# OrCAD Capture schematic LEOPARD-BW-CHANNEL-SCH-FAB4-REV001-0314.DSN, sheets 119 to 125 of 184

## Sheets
119 052_DDR4 DIMM CPU0 CHA-1: size A3; title: DDR4 DIMM CPU0 CHA-1
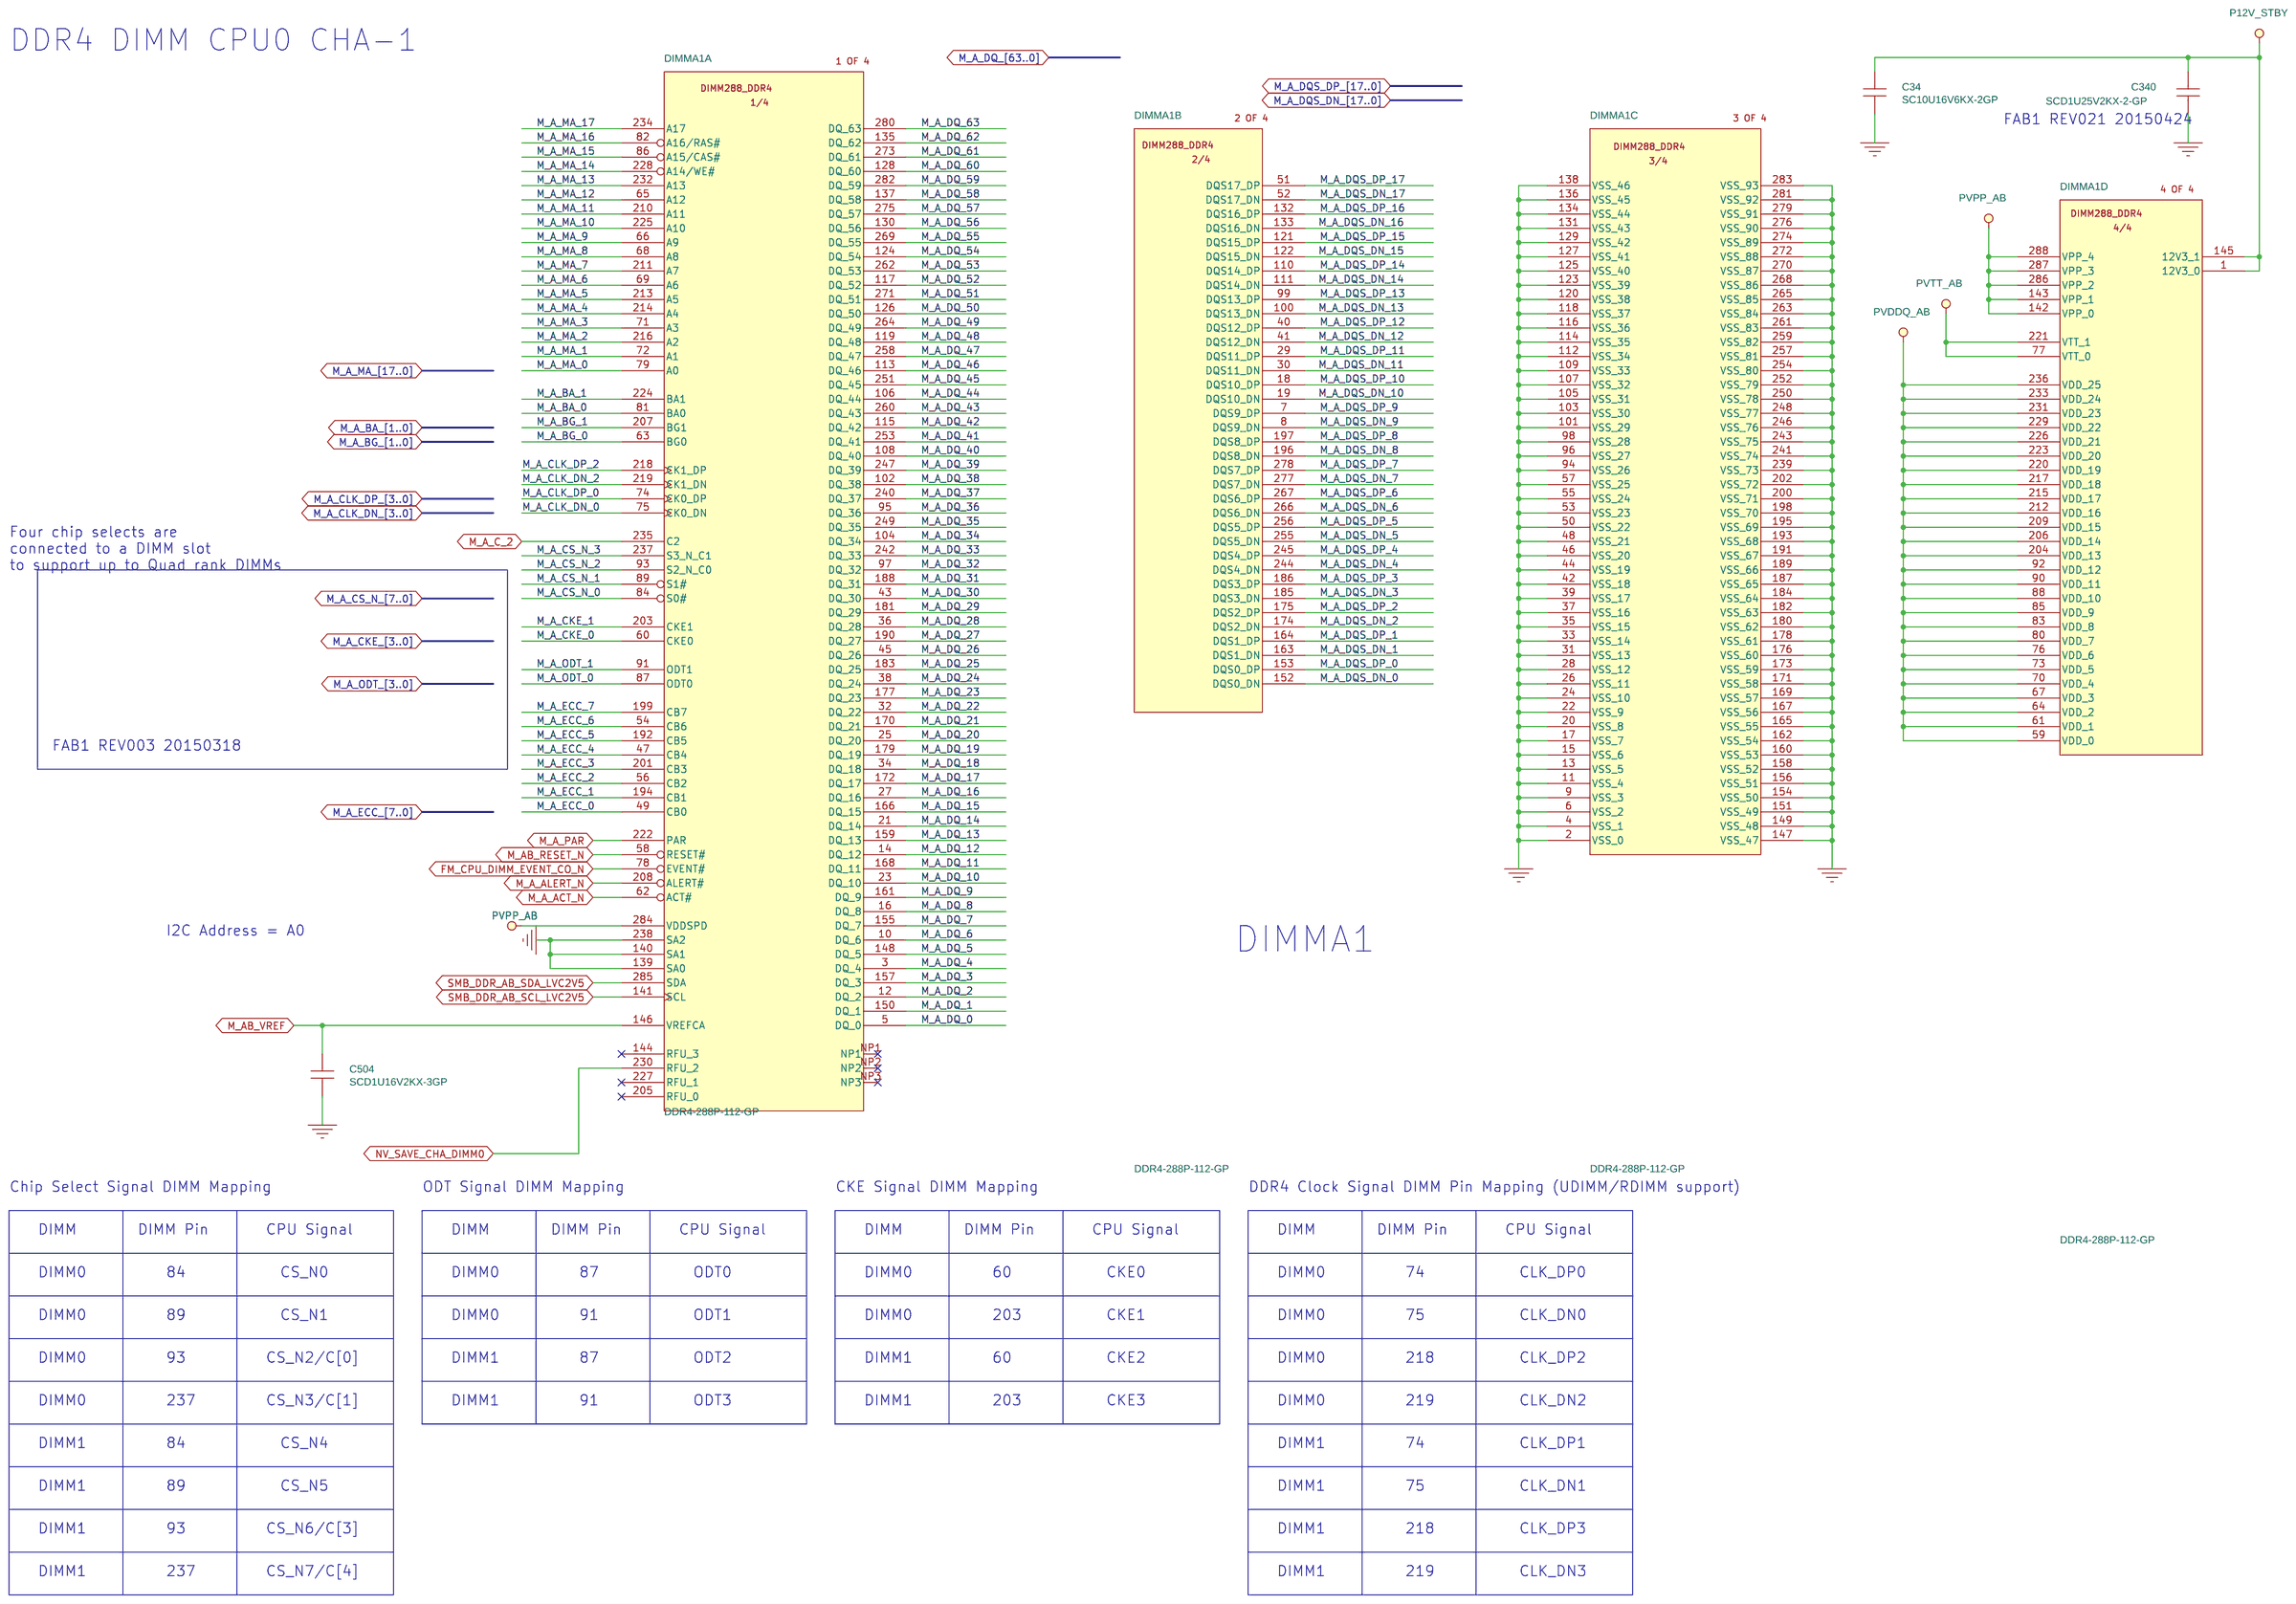
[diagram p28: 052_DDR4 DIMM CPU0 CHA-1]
120 049_CPU2 - VCCIN & VDDQ: size A3; title: CPU2 - VCCIN & VDDQ
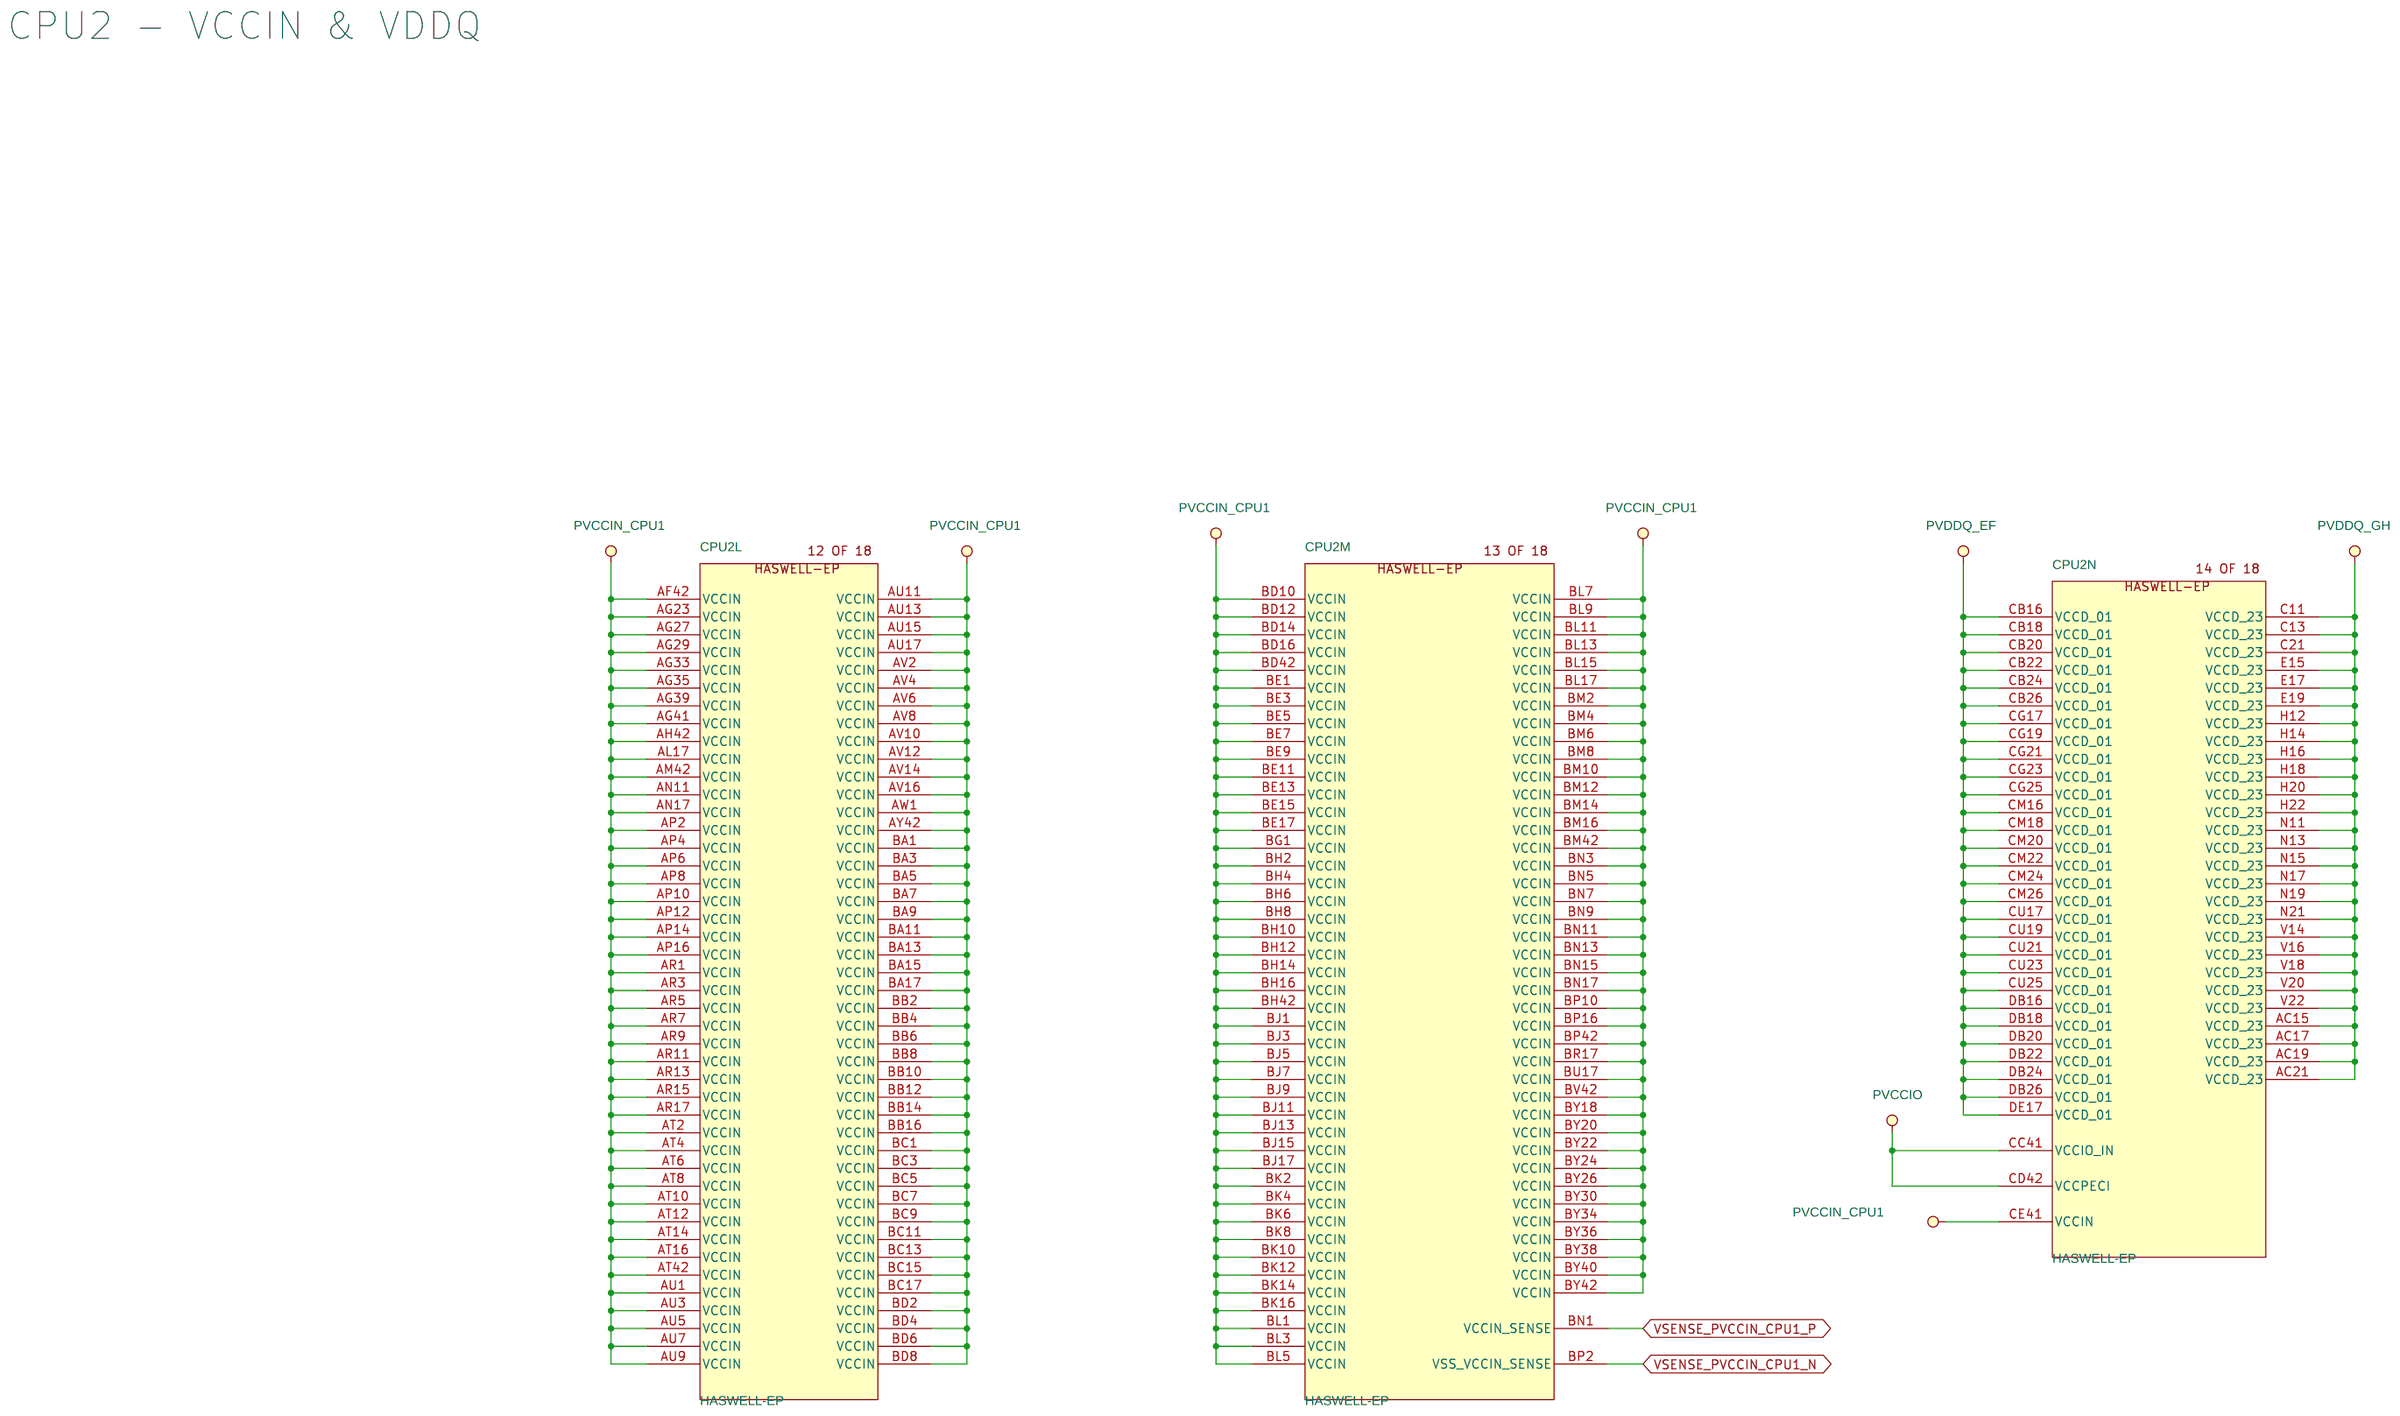
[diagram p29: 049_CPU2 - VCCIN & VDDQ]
121 046_CPU2 - PCIE (3A-3D): size A3; title: CPU2 - PCIE (3A-3D)
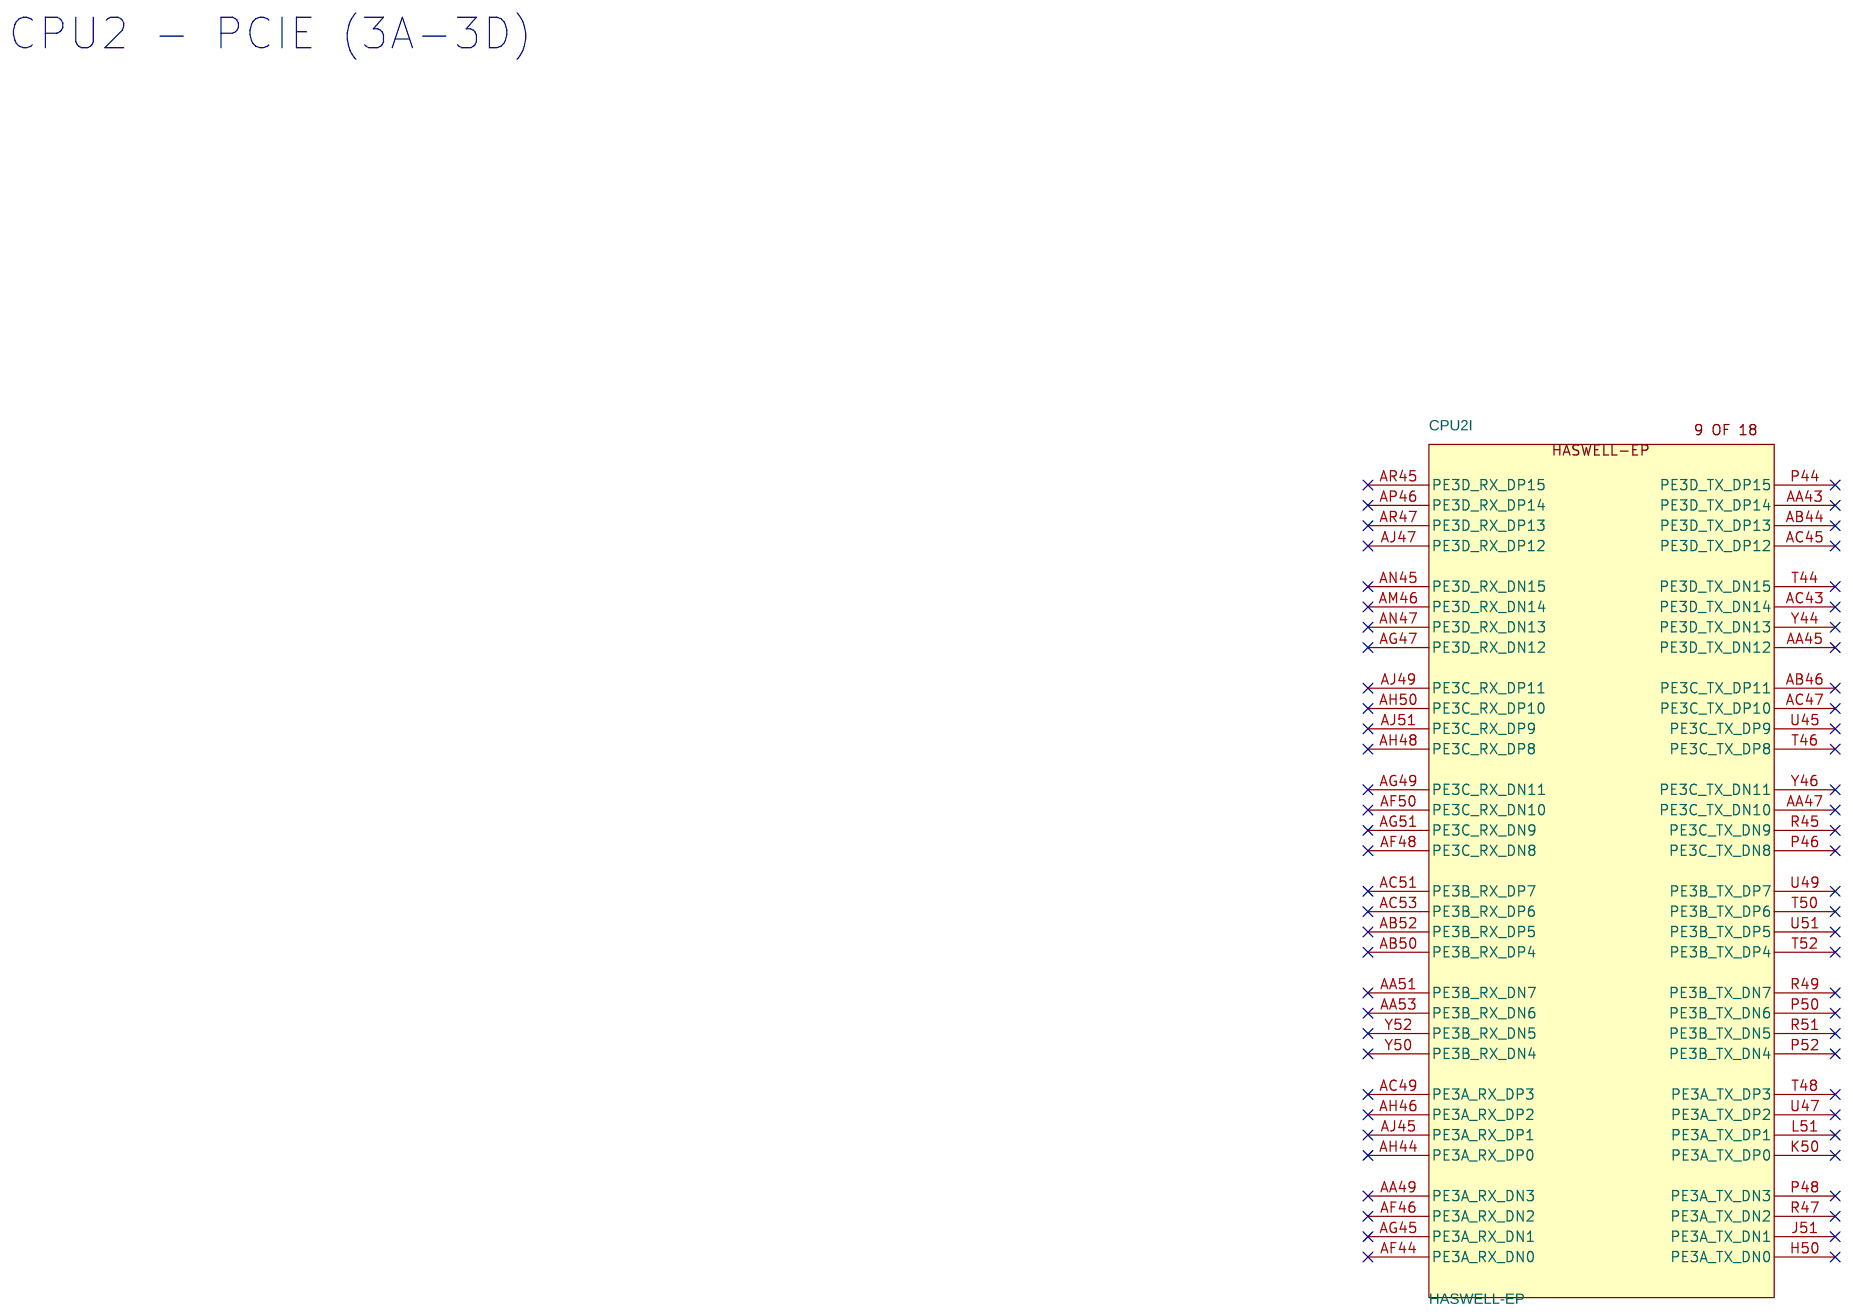
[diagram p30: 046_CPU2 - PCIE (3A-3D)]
122 045_CPU2 - PCIE (2A-2D): size A3; title: CPU2 - PCIE (2A-2D)
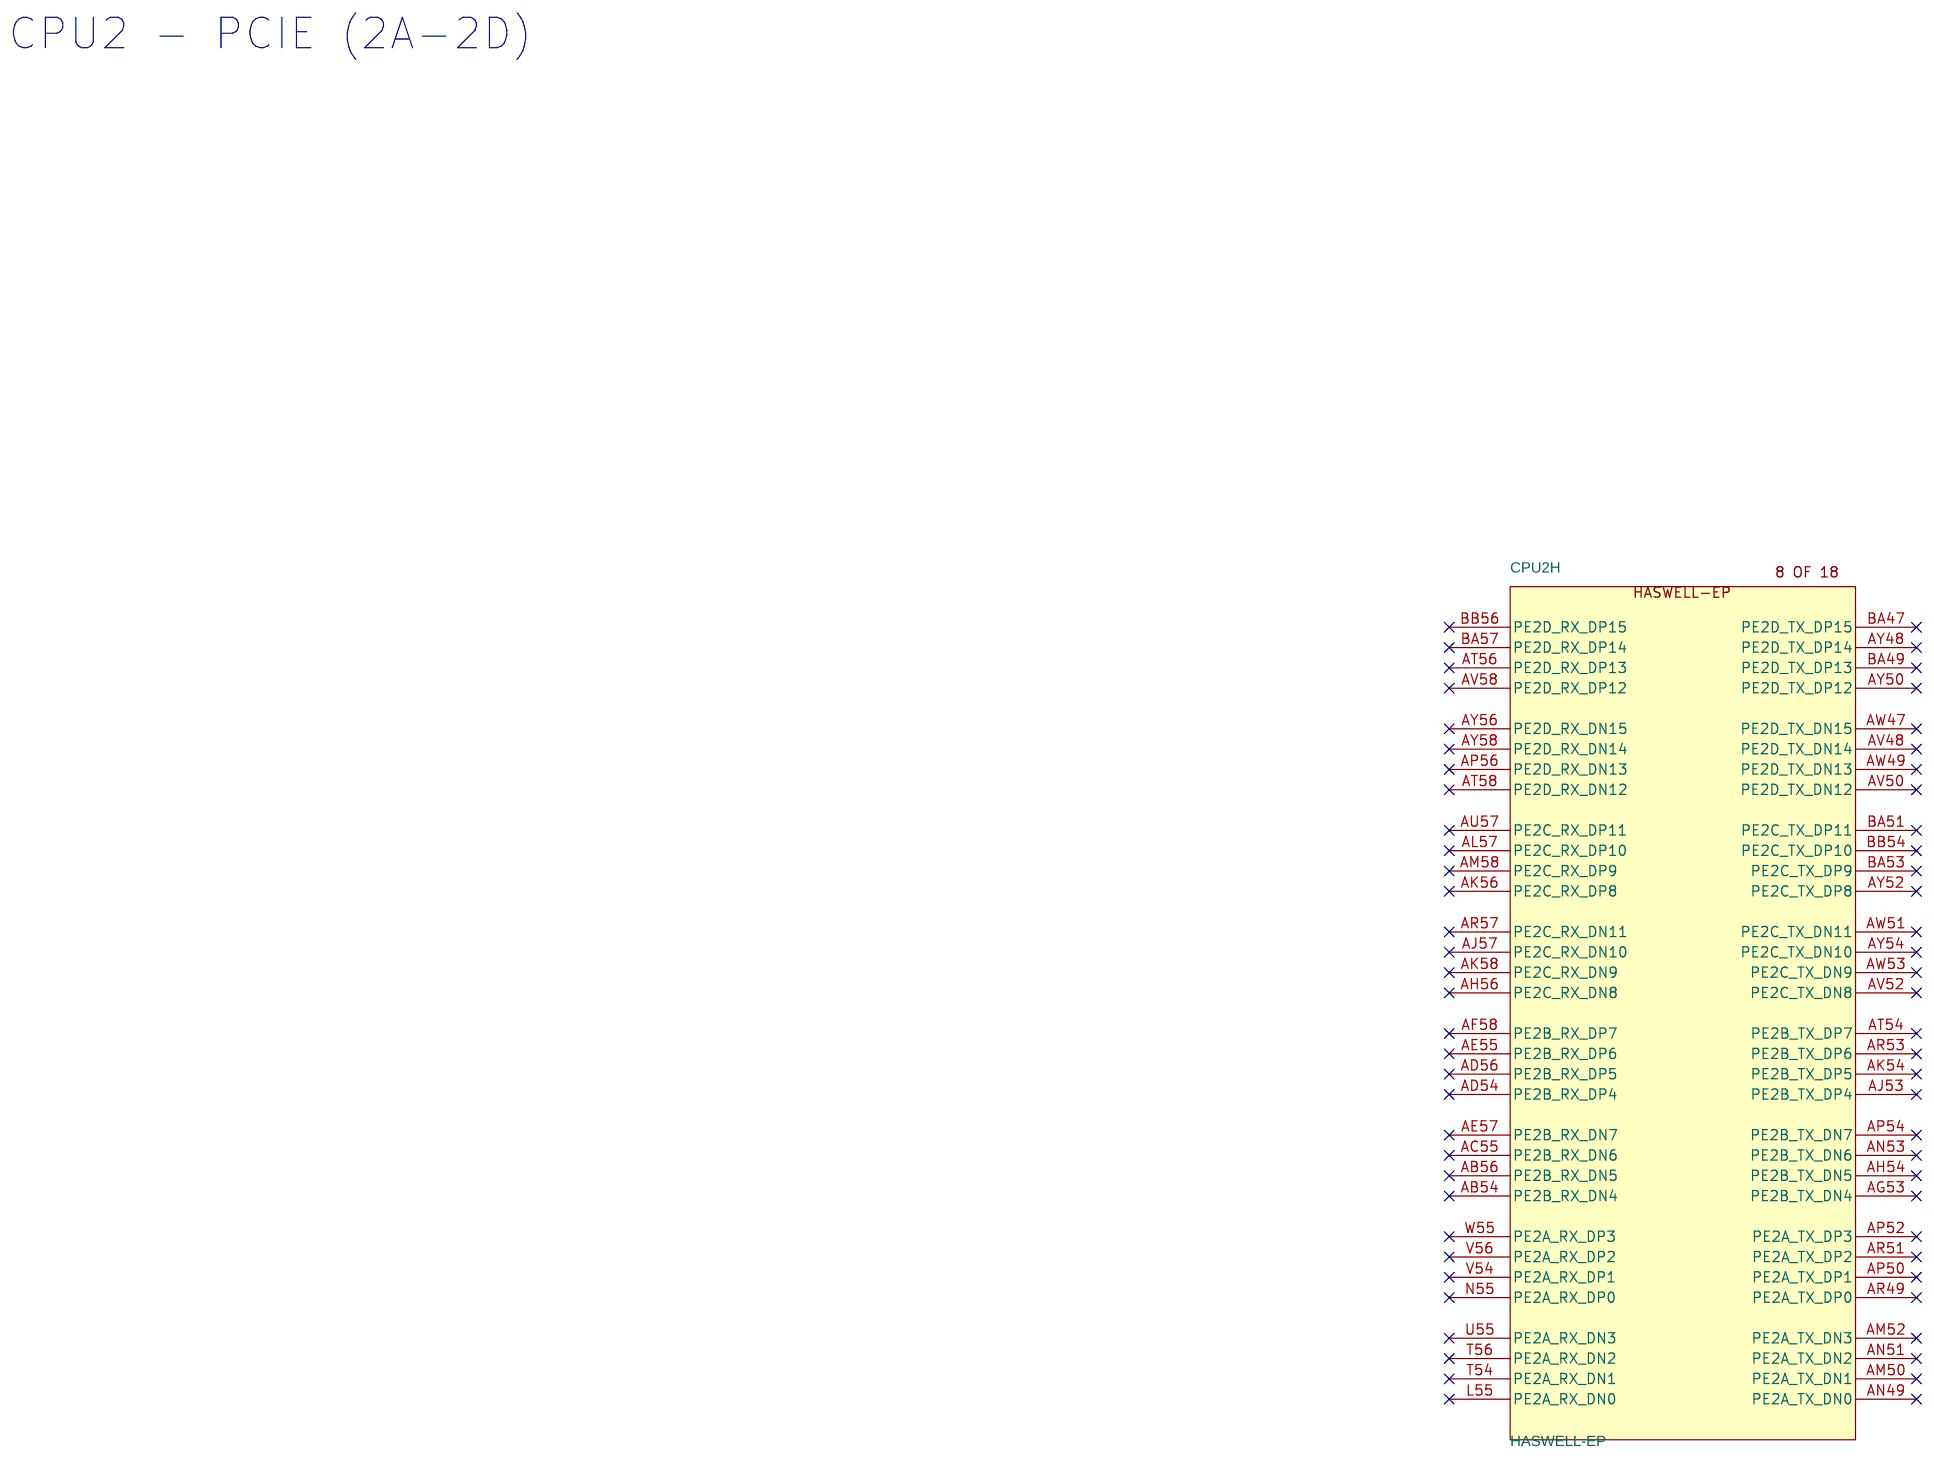
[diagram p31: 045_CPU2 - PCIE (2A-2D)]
123 044_CPU2 - DMI & PCIE (1A-1B): size A3; title: CPU2 - DMI & PCIE (1A-1B)
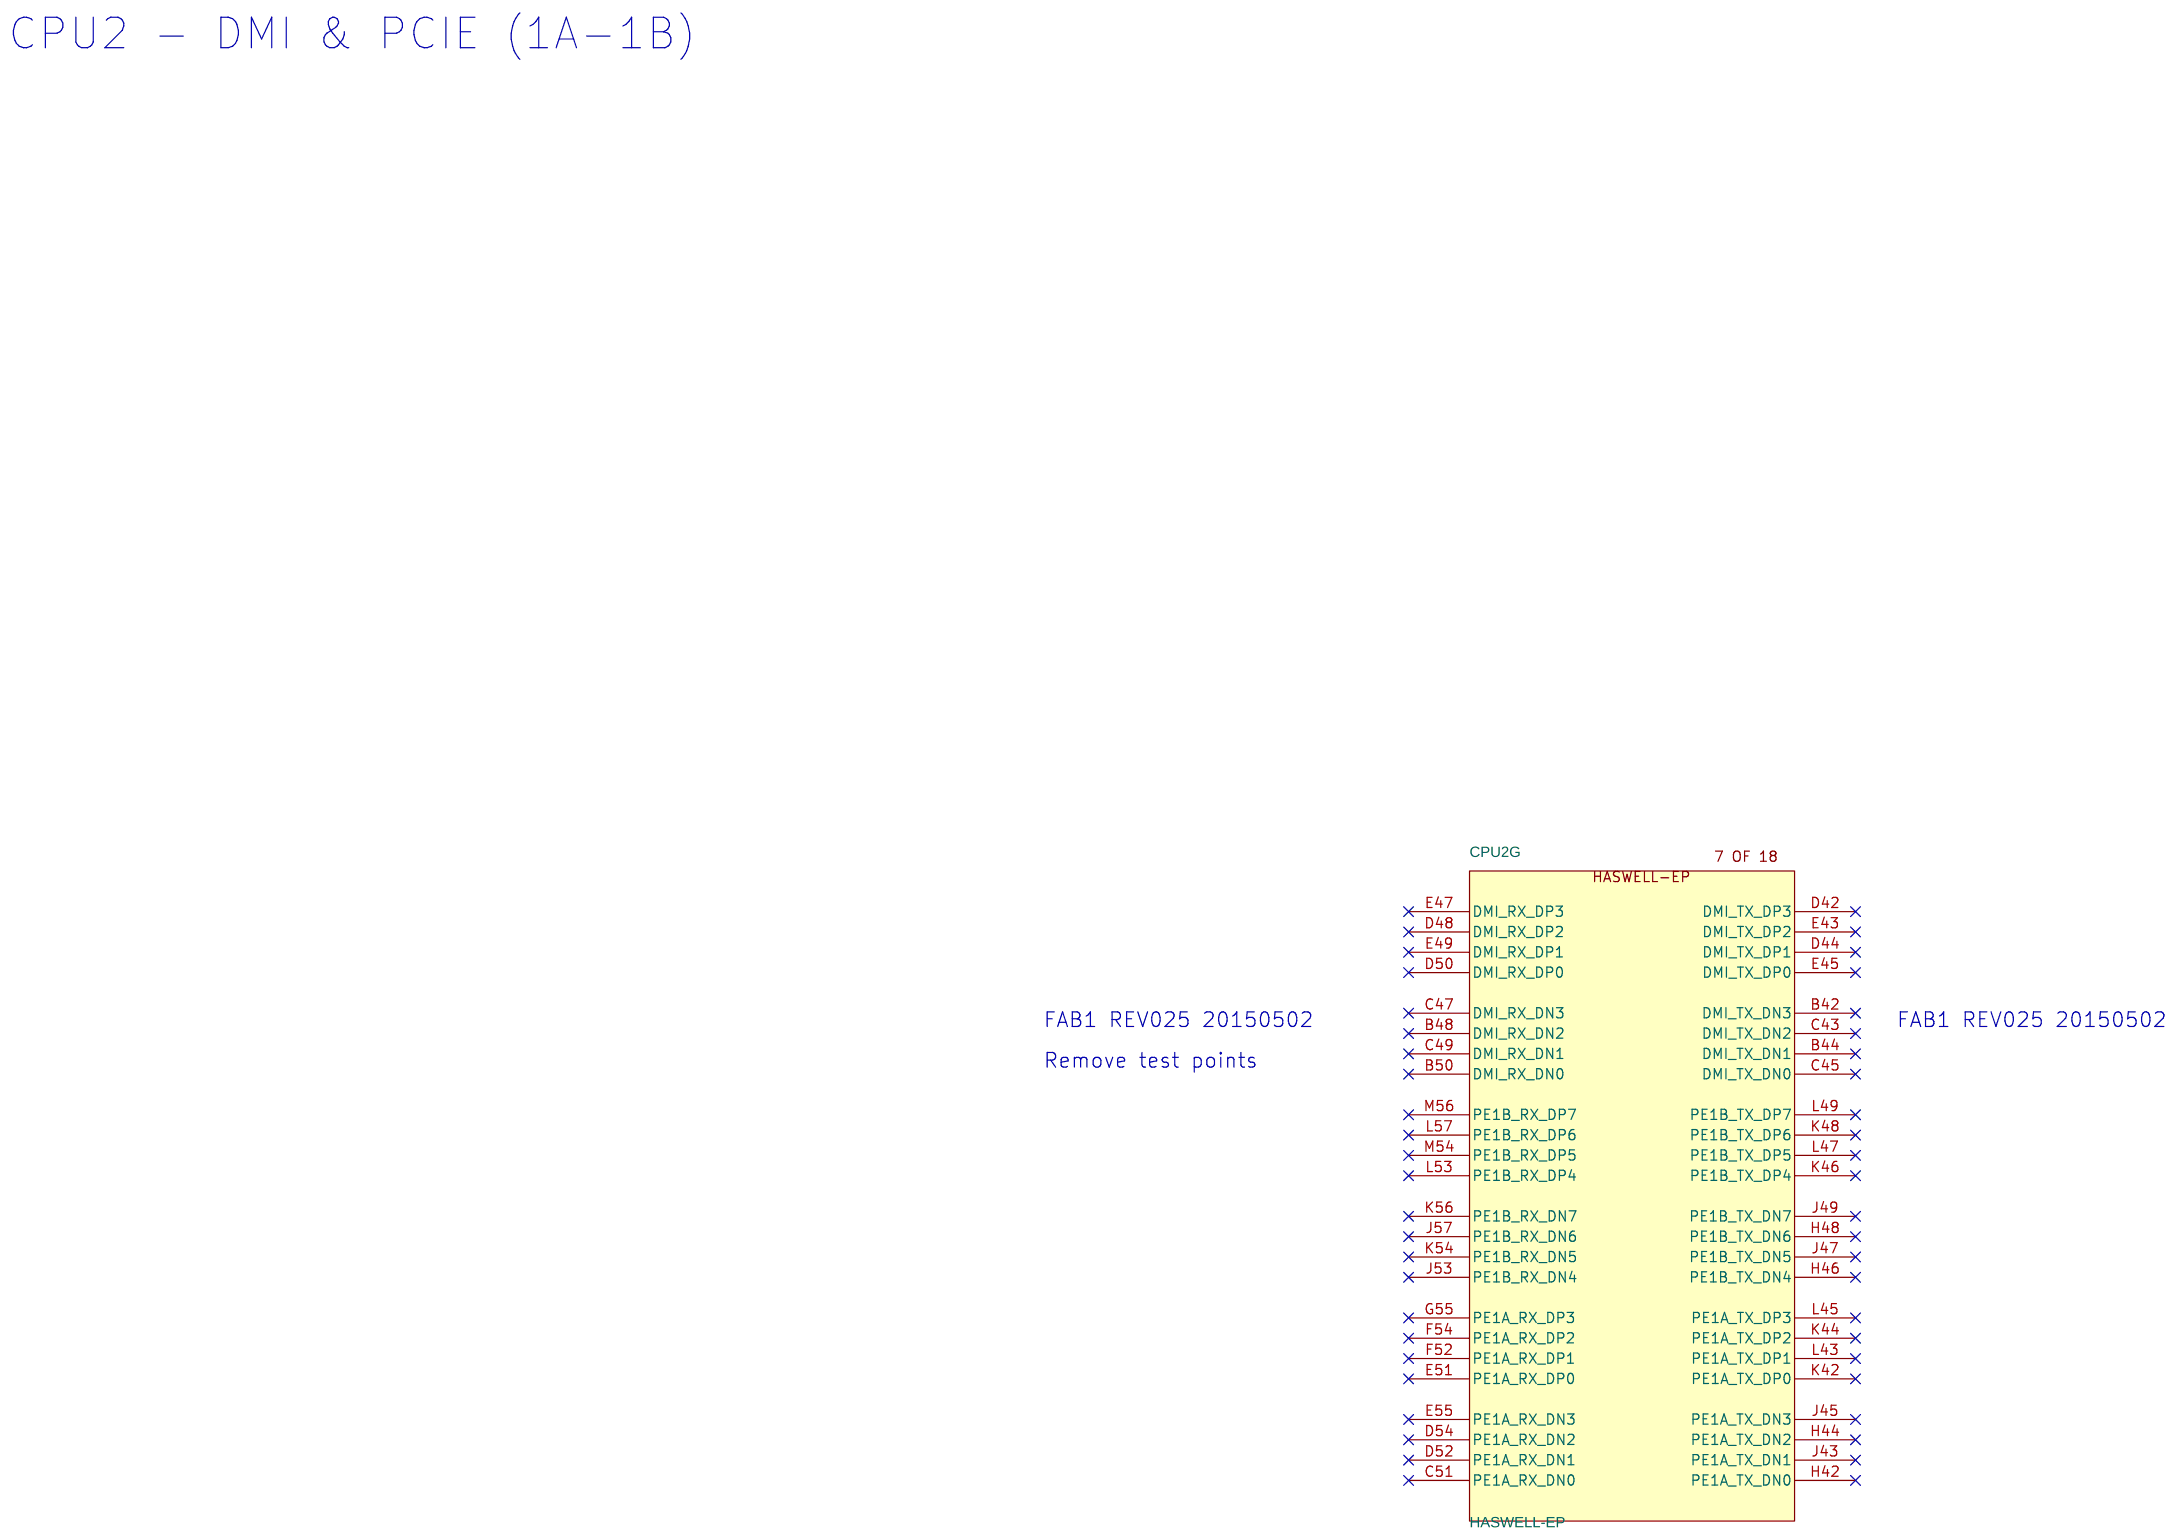
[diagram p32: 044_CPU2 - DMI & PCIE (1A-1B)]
124 043_CPU2 - DDR4 (CHANNEL H): size A3; title: CPU2 - DDR4 (CHANNEL H)
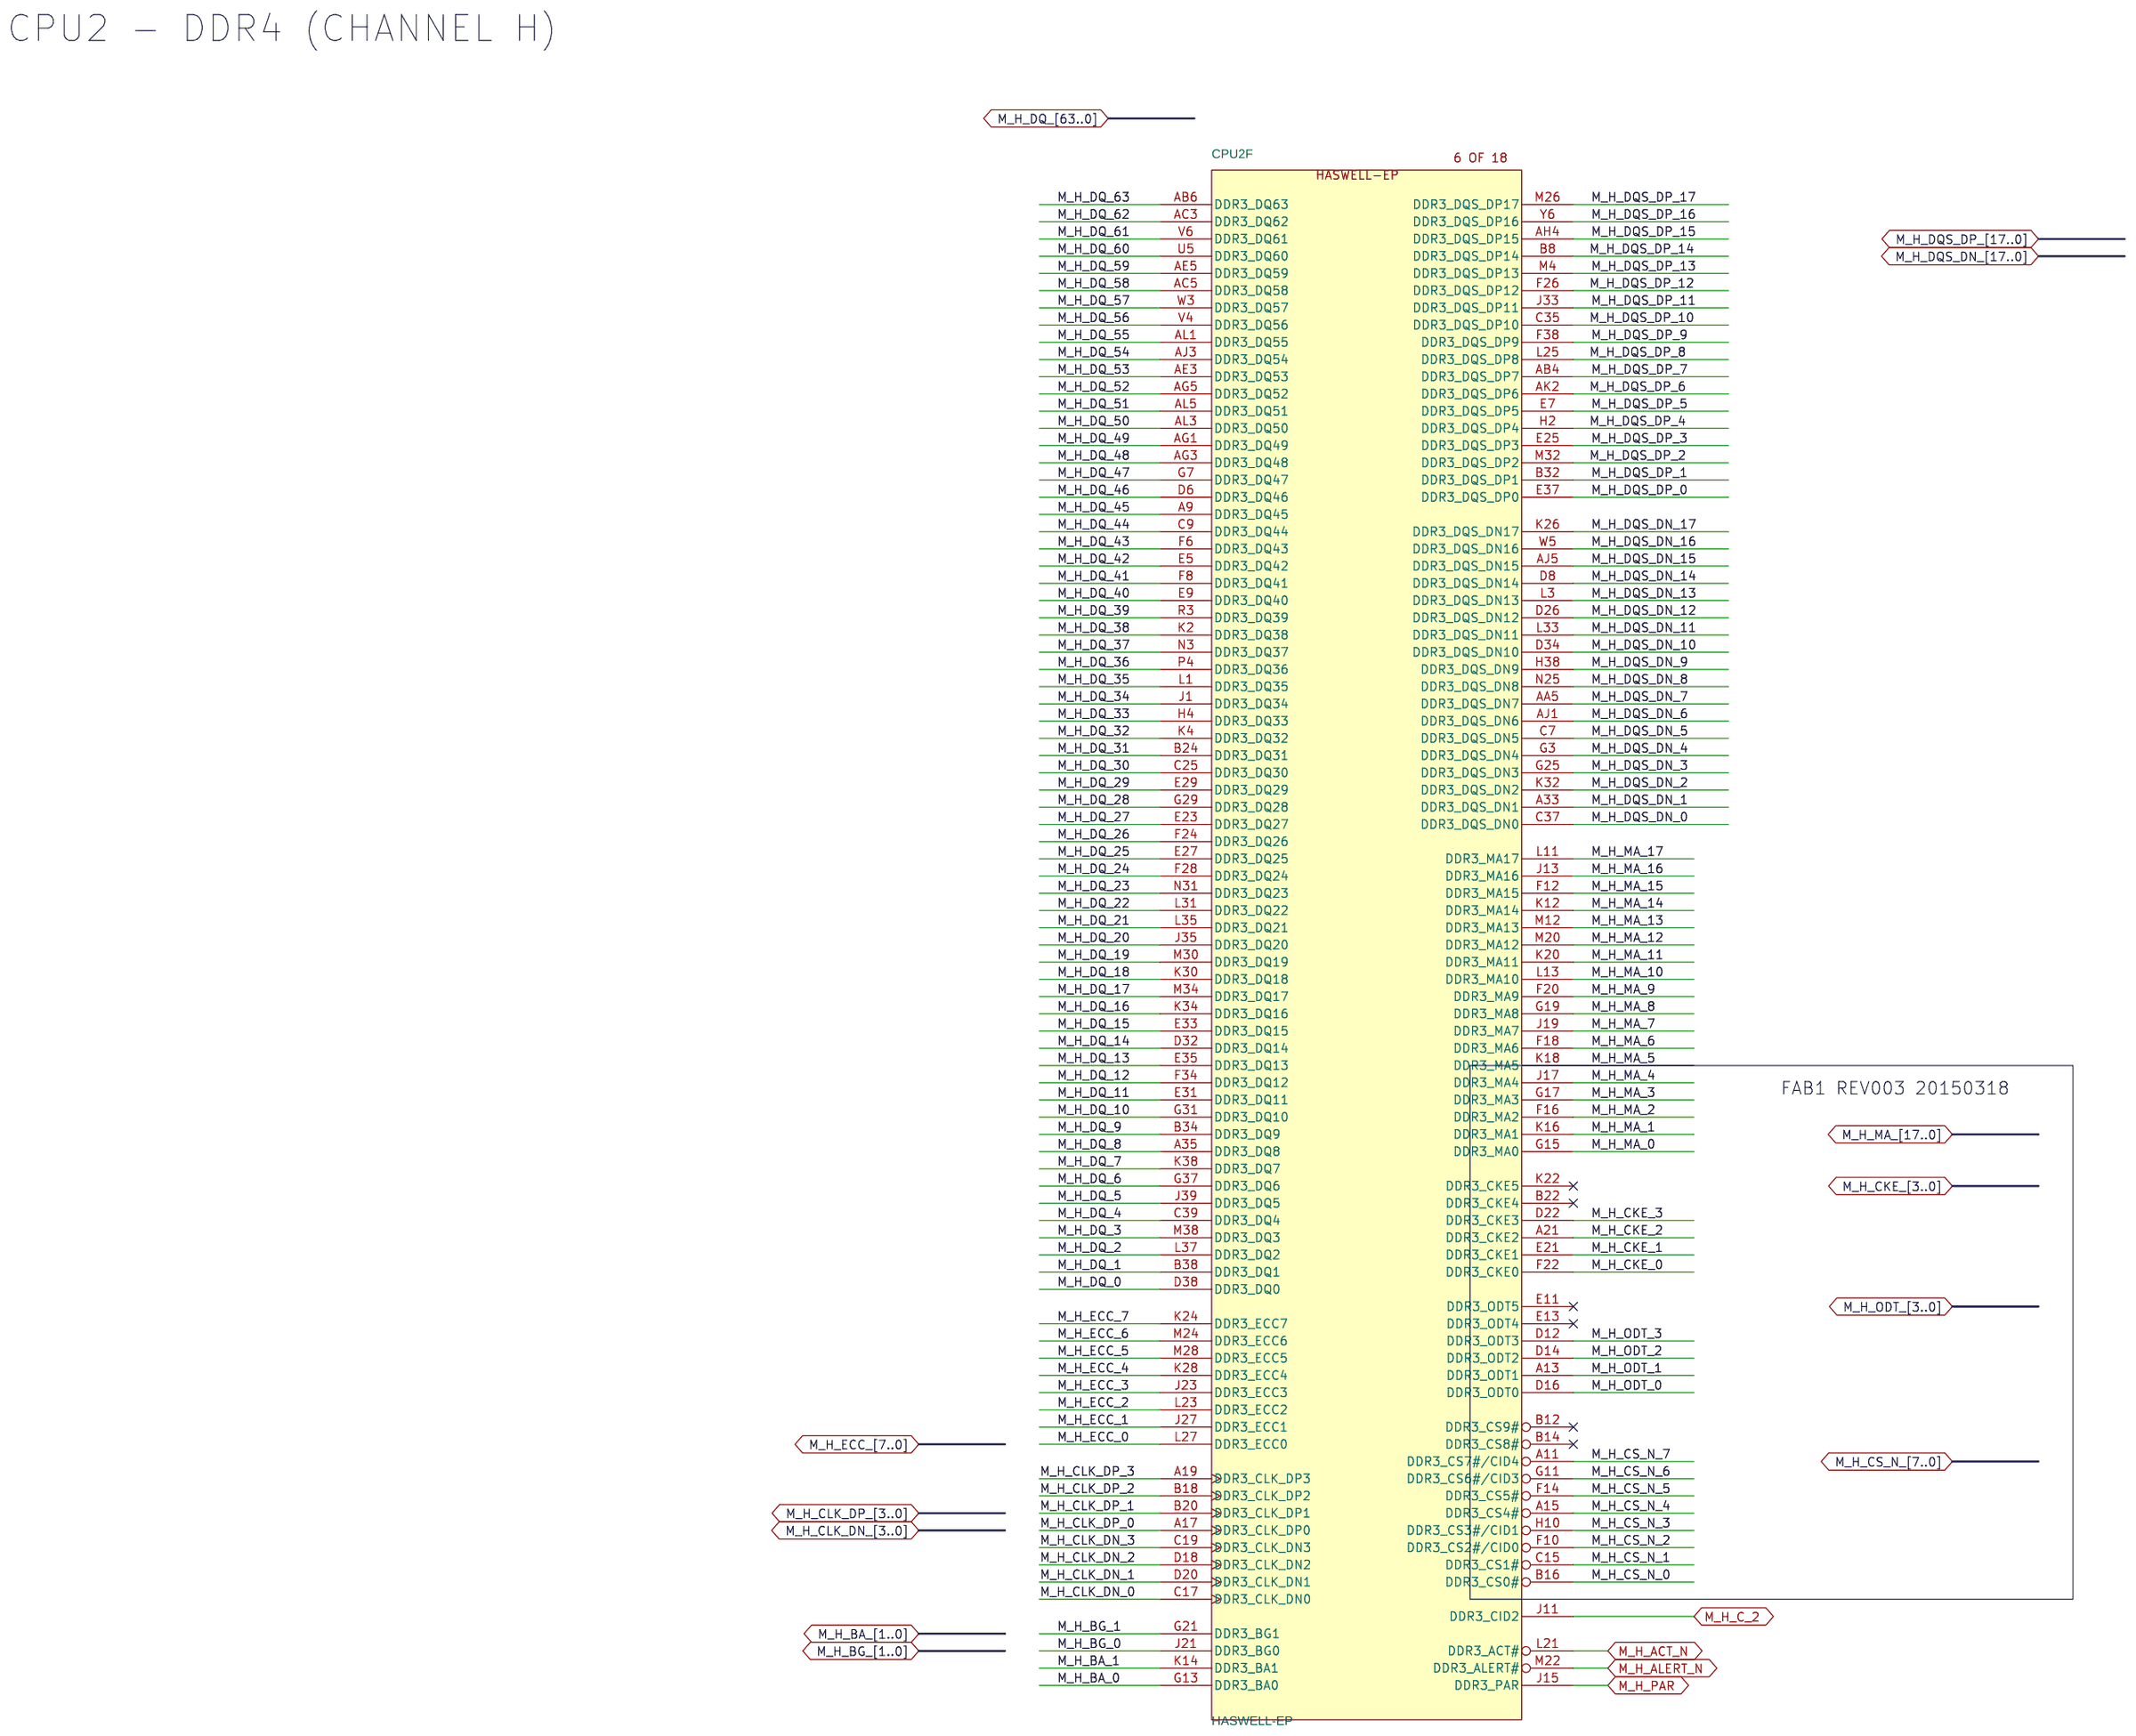
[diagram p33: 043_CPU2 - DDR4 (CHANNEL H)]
125 042_CPU2 - DDR4 (CHANNEL G): size A3; title: CPU2 - DDR4 (CHANNEL G)
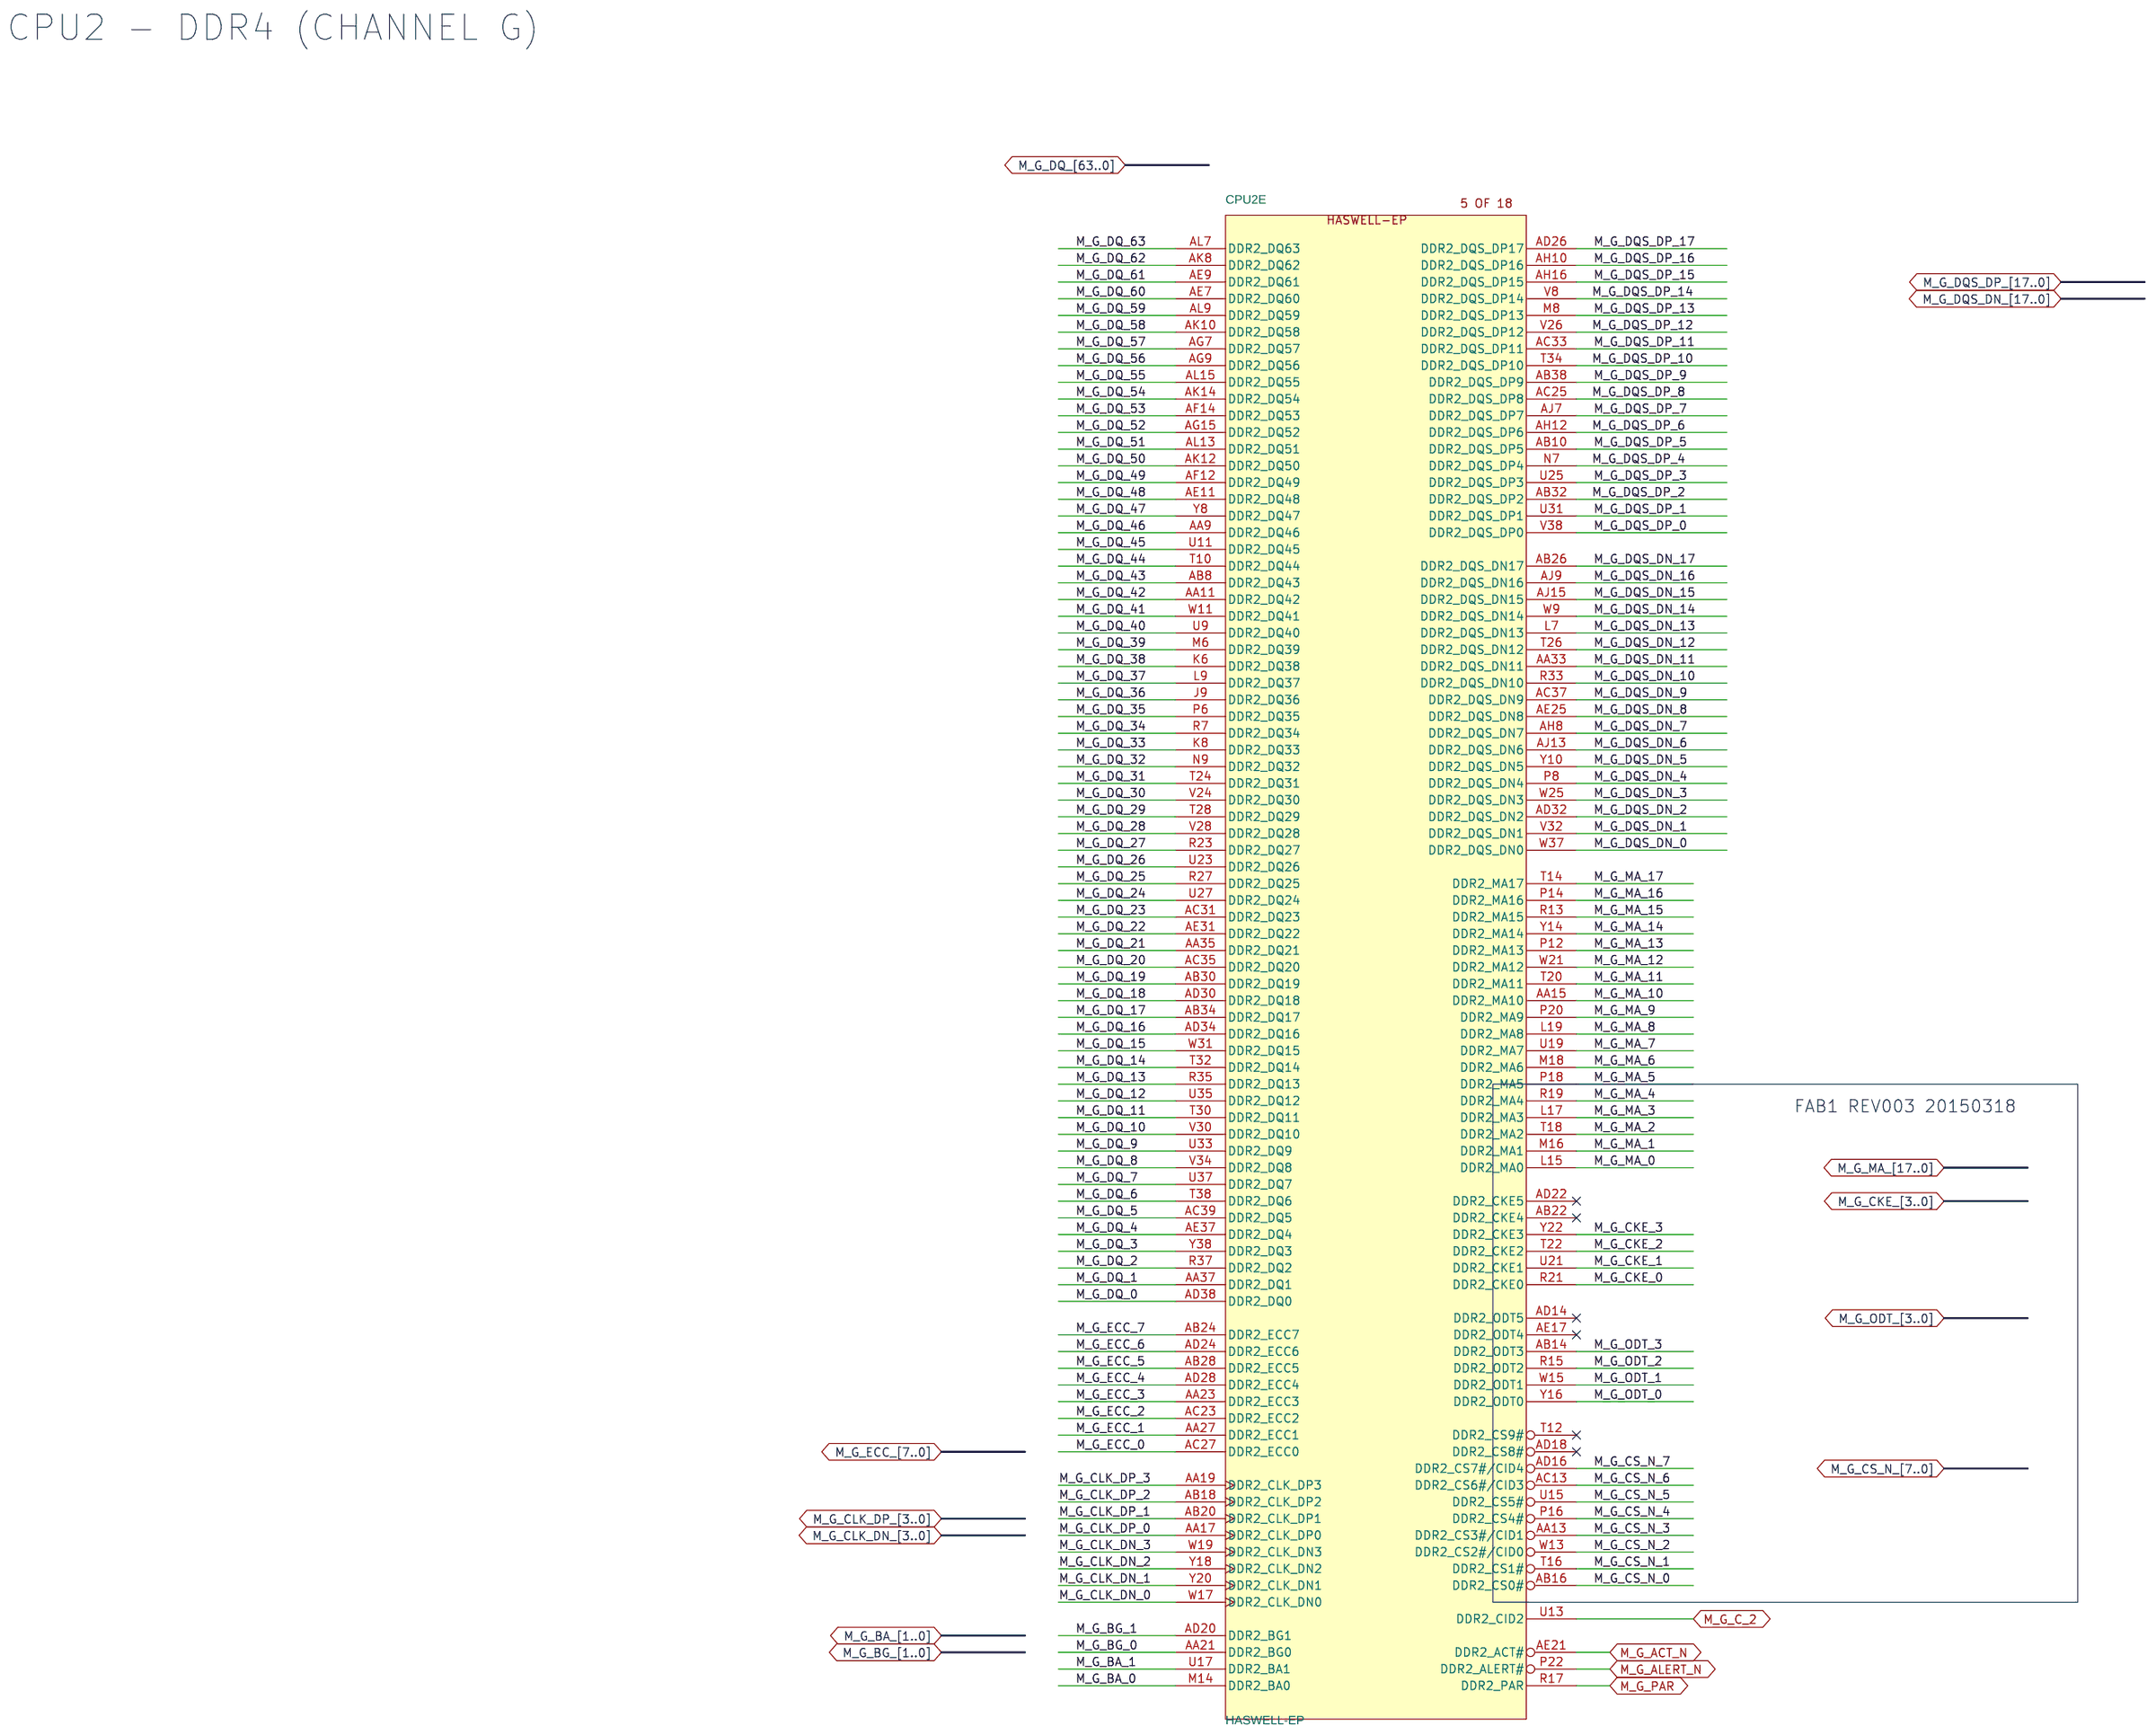
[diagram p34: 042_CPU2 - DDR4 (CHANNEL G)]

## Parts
sheet 041_CPU2 - DDR4 (CHANNEL F)
CPU2  HASWELL-EP  [SKT-LGA2011M6151-1H298]  (sections A,B,C,D,E,F,G,H,I,J,K,L,M,N,O,P,Q,R)
sheet 052_DDR4 DIMM CPU0 CHA-1
C34  SC10U16V6KX-2GP  [C1206H71]
C340  SCD1U25V2KX-2-GP  [C402H22]
C504  SCD1U16V2KX-3GP  [C402H22]
DIMMA1  DDR4-288P-112-GP  [10124632-0001113LF]  (sections A,B,C,D)

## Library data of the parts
CPU2 = HASWELL-EP: SKT CPU LGA 2011P AZIF0001-P004C SMD; GREENDFACTOR: R2_C;; POP?: 62.10079.311; Package Type: SOCKET-G2; Part Number: 62.10079.261; SPEC: http://wpqssvr.wistron.com.tw:7001/wpqs/servlet/COM.qpart.Attachment?PartNumber=62.10079.261
C34 = SC10U16V6KX-2GP: CHIP CAP C 10U 16V K1206 X7R; GREENDFACTOR: R2_SA;HF_SA;G_SA;; Part Number: 78.10621.22L; Part Type: SMD-BCG; SPEC: http://wpqssvr.wistron.com.tw:7001/wpqs/servlet/COM.qpart.Attachment?PartNumber=78.10621.22L
C340 = SCD1U25V2KX-2-GP: CHIP CAP C 0.1U 25V K0402 X7R; GREENDFACTOR: R2_SA;HF_SA;G_SA;; Part Number: 78.10422.2FL; Part Type: SMD-BCG4; SPEC: http://wpqssvr.wistron.com.tw:7001/wpqs/servlet/COM.qpart.Attachment?PartNumber=78.10422.2FL
C504 = SCD1U16V2KX-3GP: CHIP CAP C 0.1U 16V K0402 X7R; CATEGORIES: CAP_1.xV; GREENDFACTOR: R2_SA;HF_SA;G_SA;; MAIN_SOURCE: M; Part Number: 78.10421.2FL; Part Type: SMD-BCG; SPEC: http://wpqssvr.wistron.com.tw:7001/wpqs/servlet/COM.qpart.Attachment?PartNumber=78.10421.2FL
DIMMA1 = DDR4-288P-112-GP: SKT DIMM DDR4 288P 10124632-0003001LF; GREENDFACTOR: R2_C;; POP?: 022.10010.0E11; Part Number: 022.10010.0B91; Part Type: SOCKET-G2; SPEC: http://wpqssvr.wistron.com.tw:7001/wpqs/servlet/COM.qpart.Attachment?PartNumber=022.10010.0B91

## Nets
GND: C34.2 C340.2 C504.2 DIMMA1.2(VSS_0) DIMMA1.4(VSS_1) DIMMA1.6(VSS_2) DIMMA1.9(VSS_3) DIMMA1.11(VSS_4) DIMMA1.13(VSS_5) DIMMA1.15(VSS_6) DIMMA1.17(VSS_7) DIMMA1.20(VSS_8) DIMMA1.22(VSS_9) DIMMA1.24(VSS_10) DIMMA1.26(VSS_11) DIMMA1.28(VSS_12) DIMMA1.31(VSS_13) DIMMA1.33(VSS_14) DIMMA1.35(VSS_15) DIMMA1.37(VSS_16) DIMMA1.39(VSS_17) DIMMA1.42(VSS_18) DIMMA1.44(VSS_19) DIMMA1.46(VSS_20) DIMMA1.48(VSS_21) DIMMA1.50(VSS_22) DIMMA1.53(VSS_23) DIMMA1.55(VSS_24) DIMMA1.57(VSS_25) DIMMA1.94(VSS_26) DIMMA1.96(VSS_27) DIMMA1.98(VSS_28) DIMMA1.101(VSS_29) DIMMA1.103(VSS_30) DIMMA1.105(VSS_31) DIMMA1.107(VSS_32) DIMMA1.109(VSS_33) DIMMA1.112(VSS_34) DIMMA1.114(VSS_35) DIMMA1.116(VSS_36) DIMMA1.118(VSS_37) DIMMA1.120(VSS_38) DIMMA1.123(VSS_39) DIMMA1.125(VSS_40) DIMMA1.127(VSS_41) DIMMA1.129(VSS_42) DIMMA1.131(VSS_43) DIMMA1.134(VSS_44) DIMMA1.136(VSS_45) DIMMA1.138(VSS_46) DIMMA1.139(SA0) DIMMA1.140(SA1) DIMMA1.147(VSS_47) DIMMA1.149(VSS_48) DIMMA1.151(VSS_49) DIMMA1.154(VSS_50) DIMMA1.156(VSS_51) DIMMA1.158(VSS_52) DIMMA1.160(VSS_53) DIMMA1.162(VSS_54) DIMMA1.165(VSS_55) DIMMA1.167(VSS_56) DIMMA1.169(VSS_57) DIMMA1.171(VSS_58) DIMMA1.173(VSS_59) DIMMA1.176(VSS_60) DIMMA1.178(VSS_61) DIMMA1.180(VSS_62) DIMMA1.182(VSS_63) DIMMA1.184(VSS_64) DIMMA1.187(VSS_65) DIMMA1.189(VSS_66) DIMMA1.191(VSS_67) DIMMA1.193(VSS_68) DIMMA1.195(VSS_69) DIMMA1.198(VSS_70) DIMMA1.200(VSS_71) DIMMA1.202(VSS_72) DIMMA1.238(SA2) DIMMA1.239(VSS_73) DIMMA1.241(VSS_74) DIMMA1.243(VSS_75) DIMMA1.246(VSS_76) DIMMA1.248(VSS_77) DIMMA1.250(VSS_78) DIMMA1.252(VSS_79) DIMMA1.254(VSS_80) DIMMA1.257(VSS_81) DIMMA1.259(VSS_82) DIMMA1.261(VSS_83) DIMMA1.263(VSS_84) DIMMA1.265(VSS_85) DIMMA1.268(VSS_86) DIMMA1.270(VSS_87) DIMMA1.272(VSS_88) DIMMA1.274(VSS_89) DIMMA1.276(VSS_90) DIMMA1.279(VSS_91) DIMMA1.281(VSS_92) DIMMA1.283(VSS_93) ; also on sheet 1 2 3 4 5 6 7 8 9 10 11 12 13 14 15 16 17 18 19 20 21 22 23 24 25 26 27 28 29 30 31 32 33 34 35 36 37 38 39 44 46 47 49 50 51 52 53 54 55 56 57 58 59 60 61 62 63 64 65 66 69 70 71 73 74 75 76 78 79 80 81 82 83 84 86 87 88 89 90 91 92 93 94 95 96 97 98 99 100 101 102 103 104 105 106 107 108 109 110 111 112 113 114 115 116 117 118 128 129 138 139 159 160 161 166 168 169 170 171 172 173 174 175 176 177 180 181 182 183 184
P12V_STBY: C34.1 C340.1 DIMMA1.1(12V3_0) DIMMA1.145(12V3_1) ; also on sheet 2 3 4 7 9 10 11 12 13 17 18 22 23 27 28 32 36 59 60 75 95 104 105 106 107 108 109 110 111 112 113 114 115 116 117 118
PVCCIN_CPU1: CPU2.AF42(VCCIN) CPU2.AG23(VCCIN) CPU2.AG27(VCCIN) CPU2.AG29(VCCIN) CPU2.AG33(VCCIN) CPU2.AG35(VCCIN) CPU2.AG39(VCCIN) CPU2.AG41(VCCIN) CPU2.AH42(VCCIN) CPU2.AL17(VCCIN) CPU2.AM42(VCCIN) CPU2.AN11(VCCIN) CPU2.AN17(VCCIN) CPU2.AP2(VCCIN) CPU2.AP4(VCCIN) CPU2.AP6(VCCIN) CPU2.AP8(VCCIN) CPU2.AP10(VCCIN) CPU2.AP12(VCCIN) CPU2.AP14(VCCIN) CPU2.AP16(VCCIN) CPU2.AR1(VCCIN) CPU2.AR3(VCCIN) CPU2.AR5(VCCIN) CPU2.AR7(VCCIN) CPU2.AR9(VCCIN) CPU2.AR11(VCCIN) CPU2.AR13(VCCIN) CPU2.AR15(VCCIN) CPU2.AR17(VCCIN) CPU2.AT2(VCCIN) CPU2.AT4(VCCIN) CPU2.AT6(VCCIN) CPU2.AT8(VCCIN) CPU2.AT10(VCCIN) CPU2.AT12(VCCIN) CPU2.AT14(VCCIN) CPU2.AT16(VCCIN) CPU2.AT42(VCCIN) CPU2.AU1(VCCIN) CPU2.AU3(VCCIN) CPU2.AU5(VCCIN) CPU2.AU7(VCCIN) CPU2.AU9(VCCIN) CPU2.AU11(VCCIN) CPU2.AU13(VCCIN) CPU2.AU15(VCCIN) CPU2.AU17(VCCIN) CPU2.AV2(VCCIN) CPU2.AV4(VCCIN) CPU2.AV6(VCCIN) CPU2.AV8(VCCIN) CPU2.AV10(VCCIN) CPU2.AV12(VCCIN) CPU2.AV14(VCCIN) CPU2.AV16(VCCIN) CPU2.AW1(VCCIN) CPU2.AY42(VCCIN) CPU2.BA1(VCCIN) CPU2.BA3(VCCIN) CPU2.BA5(VCCIN) CPU2.BA7(VCCIN) CPU2.BA9(VCCIN) CPU2.BA11(VCCIN) CPU2.BA13(VCCIN) CPU2.BA15(VCCIN) CPU2.BA17(VCCIN) CPU2.BB2(VCCIN) CPU2.BB4(VCCIN) CPU2.BB6(VCCIN) CPU2.BB8(VCCIN) CPU2.BB10(VCCIN) CPU2.BB12(VCCIN) CPU2.BB14(VCCIN) CPU2.BB16(VCCIN) CPU2.BC1(VCCIN) CPU2.BC3(VCCIN) CPU2.BC5(VCCIN) CPU2.BC7(VCCIN) CPU2.BC9(VCCIN) CPU2.BC11(VCCIN) CPU2.BC13(VCCIN) CPU2.BC15(VCCIN) CPU2.BC17(VCCIN) CPU2.BD2(VCCIN) CPU2.BD4(VCCIN) CPU2.BD6(VCCIN) CPU2.BD8(VCCIN) CPU2.BD10(VCCIN) CPU2.BD12(VCCIN) CPU2.BD14(VCCIN) CPU2.BD16(VCCIN) CPU2.BD42(VCCIN) CPU2.BE1(VCCIN) CPU2.BE3(VCCIN) CPU2.BE5(VCCIN) CPU2.BE7(VCCIN) CPU2.BE9(VCCIN) CPU2.BE11(VCCIN) CPU2.BE13(VCCIN) CPU2.BE15(VCCIN) CPU2.BE17(VCCIN) CPU2.BG1(VCCIN) CPU2.BH2(VCCIN) CPU2.BH4(VCCIN) CPU2.BH6(VCCIN) CPU2.BH8(VCCIN) CPU2.BH10(VCCIN) CPU2.BH12(VCCIN) CPU2.BH14(VCCIN) CPU2.BH16(VCCIN) CPU2.BH42(VCCIN) CPU2.BJ1(VCCIN) CPU2.BJ3(VCCIN) CPU2.BJ5(VCCIN) CPU2.BJ7(VCCIN) CPU2.BJ9(VCCIN) CPU2.BJ11(VCCIN) CPU2.BJ13(VCCIN) CPU2.BJ15(VCCIN) CPU2.BJ17(VCCIN) CPU2.BK2(VCCIN) CPU2.BK4(VCCIN) CPU2.BK6(VCCIN) CPU2.BK8(VCCIN) CPU2.BK10(VCCIN) CPU2.BK12(VCCIN) CPU2.BK14(VCCIN) CPU2.BK16(VCCIN) CPU2.BL1(VCCIN) CPU2.BL3(VCCIN) CPU2.BL5(VCCIN) CPU2.BL7(VCCIN) CPU2.BL9(VCCIN) CPU2.BL11(VCCIN) CPU2.BL13(VCCIN) CPU2.BL15(VCCIN) CPU2.BL17(VCCIN) CPU2.BM2(VCCIN) CPU2.BM4(VCCIN) CPU2.BM6(VCCIN) CPU2.BM8(VCCIN) CPU2.BM10(VCCIN) CPU2.BM12(VCCIN) CPU2.BM14(VCCIN) CPU2.BM16(VCCIN) CPU2.BM42(VCCIN) CPU2.BN3(VCCIN) CPU2.BN5(VCCIN) CPU2.BN7(VCCIN) CPU2.BN9(VCCIN) CPU2.BN11(VCCIN) CPU2.BN13(VCCIN) CPU2.BN15(VCCIN) CPU2.BN17(VCCIN) CPU2.BP10(VCCIN) CPU2.BP16(VCCIN) CPU2.BP42(VCCIN) CPU2.BR17(VCCIN) CPU2.BU17(VCCIN) CPU2.BV42(VCCIN) CPU2.BY18(VCCIN) CPU2.BY20(VCCIN) CPU2.BY22(VCCIN) CPU2.BY24(VCCIN) CPU2.BY26(VCCIN) CPU2.BY30(VCCIN) CPU2.BY34(VCCIN) CPU2.BY36(VCCIN) CPU2.BY38(VCCIN) CPU2.BY40(VCCIN) CPU2.BY42(VCCIN) CPU2.CE41(VCCIN) ; also on sheet 32 33 34
PVCCIO: CPU2.CC41(VCCIO_IN) CPU2.CD42(VCCPECI) ; also on sheet 11 16 26 35 39 46 47 68 87 97 100 101 102 103 129 130 139 160 173 177 179 182
PVDDQ_AB: DIMMA1.59(VDD_0) DIMMA1.61(VDD_1) DIMMA1.64(VDD_2) DIMMA1.67(VDD_3) DIMMA1.70(VDD_4) DIMMA1.73(VDD_5) DIMMA1.76(VDD_6) DIMMA1.80(VDD_7) DIMMA1.83(VDD_8) DIMMA1.85(VDD_9) DIMMA1.88(VDD_10) DIMMA1.90(VDD_11) DIMMA1.92(VDD_12) DIMMA1.204(VDD_13) DIMMA1.206(VDD_14) DIMMA1.209(VDD_15) DIMMA1.212(VDD_16) DIMMA1.215(VDD_17) DIMMA1.217(VDD_18) DIMMA1.220(VDD_19) DIMMA1.223(VDD_20) DIMMA1.226(VDD_21) DIMMA1.229(VDD_22) DIMMA1.231(VDD_23) DIMMA1.233(VDD_24) DIMMA1.236(VDD_25) ; also on sheet 28 30 45 52 97 116 117 118 130 139
PVDDQ_EF: CPU2.CB16(VCCD_01) CPU2.CB18(VCCD_01) CPU2.CB20(VCCD_01) CPU2.CB22(VCCD_01) CPU2.CB24(VCCD_01) CPU2.CB26(VCCD_01) CPU2.CG17(VCCD_01) CPU2.CG19(VCCD_01) CPU2.CG21(VCCD_01) CPU2.CG23(VCCD_01) CPU2.CG25(VCCD_01) CPU2.CM16(VCCD_01) CPU2.CM18(VCCD_01) CPU2.CM20(VCCD_01) CPU2.CM22(VCCD_01) CPU2.CM24(VCCD_01) CPU2.CM26(VCCD_01) CPU2.CU17(VCCD_01) CPU2.CU19(VCCD_01) CPU2.CU21(VCCD_01) CPU2.CU23(VCCD_01) CPU2.CU25(VCCD_01) CPU2.DB16(VCCD_01) CPU2.DB18(VCCD_01) CPU2.DB20(VCCD_01) CPU2.DB22(VCCD_01) CPU2.DB24(VCCD_01) CPU2.DB26(VCCD_01) CPU2.DE17(VCCD_01) ; also on sheet 18 20 45 97 108 109 110 111 129
PVDDQ_GH: CPU2.AC15(VCCD_23) CPU2.AC17(VCCD_23) CPU2.AC19(VCCD_23) CPU2.AC21(VCCD_23) CPU2.C11(VCCD_23) CPU2.C13(VCCD_23) CPU2.C21(VCCD_23) CPU2.E15(VCCD_23) CPU2.E17(VCCD_23) CPU2.E19(VCCD_23) CPU2.H12(VCCD_23) CPU2.H14(VCCD_23) CPU2.H16(VCCD_23) CPU2.H18(VCCD_23) CPU2.H20(VCCD_23) CPU2.H22(VCCD_23) CPU2.N11(VCCD_23) CPU2.N13(VCCD_23) CPU2.N15(VCCD_23) CPU2.N17(VCCD_23) CPU2.N19(VCCD_23) CPU2.N21(VCCD_23) CPU2.V14(VCCD_23) CPU2.V16(VCCD_23) CPU2.V18(VCCD_23) CPU2.V20(VCCD_23) CPU2.V22(VCCD_23) ; also on sheet 13 15 45 97 104 105 106 107 129
FM_CPU_DIMM_EVENT_CO_N: DIMMA1.78(EVENT#) ; also on sheet 98 104 105 106 107 108 109 110 111 112 113 114 115 116 117 118
M_A_ACT_N: DIMMA1.62(ACT#) ; also on sheet 118 137
M_A_ALERT_N: DIMMA1.208(ALERT#) ; also on sheet 118 137
M_A_BA_0: DIMMA1.81(BA0) ; also on sheet 118 137
M_A_BA_1: DIMMA1.224(BA1) ; also on sheet 118 137
M_A_BG_0: DIMMA1.63(BG0) ; also on sheet 118 137
M_A_BG_1: DIMMA1.207(BG1) ; also on sheet 118 137
M_A_C_2: DIMMA1.235(C2) ; also on sheet 118 137
M_A_CKE_0: DIMMA1.60(CKE0) ; also on sheet 137
M_A_CKE_1: DIMMA1.203(CKE1) ; also on sheet 137
M_A_CLK_DN_0: DIMMA1.75(CK0_DN) ; also on sheet 137
M_A_CLK_DN_2: DIMMA1.219(CK1_DN) ; also on sheet 137
M_A_CLK_DP_0: DIMMA1.74(CK0_DP) ; also on sheet 137
M_A_CLK_DP_2: DIMMA1.218(CK1_DP) ; also on sheet 137
M_A_CS_N_0: DIMMA1.84(S0#) ; also on sheet 137
M_A_CS_N_1: DIMMA1.89(S1#) ; also on sheet 137
M_A_CS_N_2: DIMMA1.93(S2_N_C0) ; also on sheet 137
M_A_CS_N_3: DIMMA1.237(S3_N_C1) ; also on sheet 137
M_A_DQ_0: DIMMA1.5(DQ_0) ; also on sheet 118 137
M_A_DQ_1: DIMMA1.150(DQ_1) ; also on sheet 118 137
M_A_DQ_2: DIMMA1.12(DQ_2) ; also on sheet 118 137
M_A_DQ_3: DIMMA1.157(DQ_3) ; also on sheet 118 137
M_A_DQ_4: DIMMA1.3(DQ_4) ; also on sheet 118 137
M_A_DQ_5: DIMMA1.148(DQ_5) ; also on sheet 118 137
M_A_DQ_6: DIMMA1.10(DQ_6) ; also on sheet 118 137
M_A_DQ_7: DIMMA1.155(DQ_7) ; also on sheet 118 137
M_A_DQ_8: DIMMA1.16(DQ_8) ; also on sheet 118 137
M_A_DQ_9: DIMMA1.161(DQ_9) ; also on sheet 118 137
M_A_DQ_10: DIMMA1.23(DQ_10) ; also on sheet 118 137
M_A_DQ_11: DIMMA1.168(DQ_11) ; also on sheet 118 137
M_A_DQ_12: DIMMA1.14(DQ_12) ; also on sheet 118 137
M_A_DQ_13: DIMMA1.159(DQ_13) ; also on sheet 118 137
M_A_DQ_14: DIMMA1.21(DQ_14) ; also on sheet 118 137
M_A_DQ_15: DIMMA1.166(DQ_15) ; also on sheet 118 137
M_A_DQ_16: DIMMA1.27(DQ_16) ; also on sheet 118 137
M_A_DQ_17: DIMMA1.172(DQ_17) ; also on sheet 118 137
M_A_DQ_18: DIMMA1.34(DQ_18) ; also on sheet 118 137
M_A_DQ_19: DIMMA1.179(DQ_19) ; also on sheet 118 137
M_A_DQ_20: DIMMA1.25(DQ_20) ; also on sheet 118 137
M_A_DQ_21: DIMMA1.170(DQ_21) ; also on sheet 118 137
M_A_DQ_22: DIMMA1.32(DQ_22) ; also on sheet 118 137
M_A_DQ_23: DIMMA1.177(DQ_23) ; also on sheet 118 137
M_A_DQ_24: DIMMA1.38(DQ_24) ; also on sheet 118 137
M_A_DQ_25: DIMMA1.183(DQ_25) ; also on sheet 118 137
M_A_DQ_26: DIMMA1.45(DQ_26) ; also on sheet 118 137
M_A_DQ_27: DIMMA1.190(DQ_27) ; also on sheet 118 137
M_A_DQ_28: DIMMA1.36(DQ_28) ; also on sheet 118 137
M_A_DQ_29: DIMMA1.181(DQ_29) ; also on sheet 118 137
M_A_DQ_30: DIMMA1.43(DQ_30) ; also on sheet 118 137
M_A_DQ_31: DIMMA1.188(DQ_31) ; also on sheet 118 137
M_A_DQ_32: DIMMA1.97(DQ_32) ; also on sheet 118 137
M_A_DQ_33: DIMMA1.242(DQ_33) ; also on sheet 118 137
M_A_DQ_34: DIMMA1.104(DQ_34) ; also on sheet 118 137
M_A_DQ_35: DIMMA1.249(DQ_35) ; also on sheet 118 137
M_A_DQ_36: DIMMA1.95(DQ_36) ; also on sheet 118 137
M_A_DQ_37: DIMMA1.240(DQ_37) ; also on sheet 118 137
M_A_DQ_38: DIMMA1.102(DQ_38) ; also on sheet 118 137
M_A_DQ_39: DIMMA1.247(DQ_39) ; also on sheet 118 137
M_A_DQ_40: DIMMA1.108(DQ_40) ; also on sheet 118 137
M_A_DQ_41: DIMMA1.253(DQ_41) ; also on sheet 118 137
M_A_DQ_42: DIMMA1.115(DQ_42) ; also on sheet 118 137
M_A_DQ_43: DIMMA1.260(DQ_43) ; also on sheet 118 137
M_A_DQ_44: DIMMA1.106(DQ_44) ; also on sheet 118 137
M_A_DQ_45: DIMMA1.251(DQ_45) ; also on sheet 118 137
M_A_DQ_46: DIMMA1.113(DQ_46) ; also on sheet 118 137
M_A_DQ_47: DIMMA1.258(DQ_47) ; also on sheet 118 137
M_A_DQ_48: DIMMA1.119(DQ_48) ; also on sheet 118 137
M_A_DQ_49: DIMMA1.264(DQ_49) ; also on sheet 118 137
M_A_DQ_50: DIMMA1.126(DQ_50) ; also on sheet 118 137
M_A_DQ_51: DIMMA1.271(DQ_51) ; also on sheet 118 137
M_A_DQ_52: DIMMA1.117(DQ_52) ; also on sheet 118 137
M_A_DQ_53: DIMMA1.262(DQ_53) ; also on sheet 118 137
M_A_DQ_54: DIMMA1.124(DQ_54) ; also on sheet 118 137
M_A_DQ_55: DIMMA1.269(DQ_55) ; also on sheet 118 137
M_A_DQ_56: DIMMA1.130(DQ_56) ; also on sheet 118 137
M_A_DQ_57: DIMMA1.275(DQ_57) ; also on sheet 118 137
M_A_DQ_58: DIMMA1.137(DQ_58) ; also on sheet 118 137
M_A_DQ_59: DIMMA1.282(DQ_59) ; also on sheet 118 137
M_A_DQ_60: DIMMA1.128(DQ_60) ; also on sheet 118 137
M_A_DQ_61: DIMMA1.273(DQ_61) ; also on sheet 118 137
M_A_DQ_62: DIMMA1.135(DQ_62) ; also on sheet 118 137
M_A_DQ_63: DIMMA1.280(DQ_63) ; also on sheet 118 137
M_A_DQS_DN_0: DIMMA1.152(DQS0_DN) ; also on sheet 118 137
M_A_DQS_DN_1: DIMMA1.163(DQS1_DN) ; also on sheet 118 137
M_A_DQS_DN_2: DIMMA1.174(DQS2_DN) ; also on sheet 118 137
M_A_DQS_DN_3: DIMMA1.185(DQS3_DN) ; also on sheet 118 137
M_A_DQS_DN_4: DIMMA1.244(DQS4_DN) ; also on sheet 118 137
M_A_DQS_DN_5: DIMMA1.255(DQS5_DN) ; also on sheet 118 137
M_A_DQS_DN_6: DIMMA1.266(DQS6_DN) ; also on sheet 118 137
M_A_DQS_DN_7: DIMMA1.277(DQS7_DN) ; also on sheet 118 137
M_A_DQS_DN_8: DIMMA1.196(DQS8_DN) ; also on sheet 118 137
M_A_DQS_DN_9: DIMMA1.8(DQS9_DN) ; also on sheet 118 137
M_A_DQS_DN_10: DIMMA1.19(DQS10_DN) ; also on sheet 118 137
M_A_DQS_DN_11: DIMMA1.30(DQS11_DN) ; also on sheet 118 137
M_A_DQS_DN_12: DIMMA1.41(DQS12_DN) ; also on sheet 118 137
M_A_DQS_DN_13: DIMMA1.100(DQS13_DN) ; also on sheet 118 137
M_A_DQS_DN_14: DIMMA1.111(DQS14_DN) ; also on sheet 118 137
M_A_DQS_DN_15: DIMMA1.122(DQS15_DN) ; also on sheet 118 137
M_A_DQS_DN_16: DIMMA1.133(DQS16_DN) ; also on sheet 118 137
M_A_DQS_DN_17: DIMMA1.52(DQS17_DN) ; also on sheet 118 137
M_A_DQS_DP_0: DIMMA1.153(DQS0_DP) ; also on sheet 118 137
M_A_DQS_DP_1: DIMMA1.164(DQS1_DP) ; also on sheet 118 137
M_A_DQS_DP_2: DIMMA1.175(DQS2_DP) ; also on sheet 118 137
M_A_DQS_DP_3: DIMMA1.186(DQS3_DP) ; also on sheet 118 137
M_A_DQS_DP_4: DIMMA1.245(DQS4_DP) ; also on sheet 118 137
M_A_DQS_DP_5: DIMMA1.256(DQS5_DP) ; also on sheet 118 137
M_A_DQS_DP_6: DIMMA1.267(DQS6_DP) ; also on sheet 118 137
M_A_DQS_DP_7: DIMMA1.278(DQS7_DP) ; also on sheet 118 137
M_A_DQS_DP_8: DIMMA1.197(DQS8_DP) ; also on sheet 118 137
M_A_DQS_DP_9: DIMMA1.7(DQS9_DP) ; also on sheet 118 137
M_A_DQS_DP_10: DIMMA1.18(DQS10_DP) ; also on sheet 118 137
M_A_DQS_DP_11: DIMMA1.29(DQS11_DP) ; also on sheet 118 137
M_A_DQS_DP_12: DIMMA1.40(DQS12_DP) ; also on sheet 118 137
M_A_DQS_DP_13: DIMMA1.99(DQS13_DP) ; also on sheet 118 137
M_A_DQS_DP_14: DIMMA1.110(DQS14_DP) ; also on sheet 118 137
M_A_DQS_DP_15: DIMMA1.121(DQS15_DP) ; also on sheet 118 137
M_A_DQS_DP_16: DIMMA1.132(DQS16_DP) ; also on sheet 118 137
M_A_DQS_DP_17: DIMMA1.51(DQS17_DP) ; also on sheet 118 137
M_A_ECC_0: DIMMA1.49(CB0) ; also on sheet 118 137
M_A_ECC_1: DIMMA1.194(CB1) ; also on sheet 118 137
M_A_ECC_2: DIMMA1.56(CB2) ; also on sheet 118 137
M_A_ECC_3: DIMMA1.201(CB3) ; also on sheet 118 137
M_A_ECC_4: DIMMA1.47(CB4) ; also on sheet 118 137
M_A_ECC_5: DIMMA1.192(CB5) ; also on sheet 118 137
M_A_ECC_6: DIMMA1.54(CB6) ; also on sheet 118 137
M_A_ECC_7: DIMMA1.199(CB7) ; also on sheet 118 137
M_A_MA_0: DIMMA1.79(A0) ; also on sheet 118 137
M_A_MA_1: DIMMA1.72(A1) ; also on sheet 118 137
M_A_MA_2: DIMMA1.216(A2) ; also on sheet 118 137
M_A_MA_3: DIMMA1.71(A3) ; also on sheet 118 137
M_A_MA_4: DIMMA1.214(A4) ; also on sheet 118 137
M_A_MA_5: DIMMA1.213(A5) ; also on sheet 118 137
M_A_MA_6: DIMMA1.69(A6) ; also on sheet 118 137
M_A_MA_7: DIMMA1.211(A7) ; also on sheet 118 137
M_A_MA_8: DIMMA1.68(A8) ; also on sheet 118 137
M_A_MA_9: DIMMA1.66(A9) ; also on sheet 118 137
M_A_MA_10: DIMMA1.225(A10) ; also on sheet 118 137
M_A_MA_11: DIMMA1.210(A11) ; also on sheet 118 137
M_A_MA_12: DIMMA1.65(A12) ; also on sheet 118 137
M_A_MA_13: DIMMA1.232(A13) ; also on sheet 118 137
M_A_MA_14: DIMMA1.228(A14/WE#) ; also on sheet 118 137
M_A_MA_15: DIMMA1.86(A15/CAS#) ; also on sheet 118 137
M_A_MA_16: DIMMA1.82(A16/RAS#) ; also on sheet 118 137
M_A_MA_17: DIMMA1.234(A17) ; also on sheet 118 137
M_A_ODT_0: DIMMA1.87(ODT0) ; also on sheet 137
M_A_ODT_1: DIMMA1.91(ODT1) ; also on sheet 137
M_A_PAR: DIMMA1.222(PAR) ; also on sheet 118 137
M_AB_RESET_N: DIMMA1.58(RESET#) ; also on sheet 116 117 118 139
M_AB_VREF: C504.1 DIMMA1.146(VREFCA) ; also on sheet 116 117 118 139
M_G_ACT_N: CPU2.AE21(DDR2_ACT#) ; also on sheet 106 107
M_G_ALERT_N: CPU2.P22(DDR2_ALERT#) ; also on sheet 106 107
M_G_BA_0: CPU2.M14(DDR2_BA0) ; also on sheet 106 107
M_G_BA_1: CPU2.U17(DDR2_BA1) ; also on sheet 106 107
M_G_BG_0: CPU2.AA21(DDR2_BG0) ; also on sheet 106 107
M_G_BG_1: CPU2.AD20(DDR2_BG1) ; also on sheet 106 107
M_G_C_2: CPU2.U13(DDR2_CID2) ; also on sheet 106 107
M_G_CKE_0: CPU2.R21(DDR2_CKE0) ; also on sheet 107
M_G_CKE_1: CPU2.U21(DDR2_CKE1) ; also on sheet 107
M_G_CKE_2: CPU2.T22(DDR2_CKE2) ; also on sheet 106
M_G_CKE_3: CPU2.Y22(DDR2_CKE3) ; also on sheet 106
M_G_CLK_DN_0: CPU2.W17(DDR2_CLK_DN0) ; also on sheet 107
M_G_CLK_DN_1: CPU2.Y20(DDR2_CLK_DN1) ; also on sheet 106
M_G_CLK_DN_2: CPU2.Y18(DDR2_CLK_DN2) ; also on sheet 107
M_G_CLK_DN_3: CPU2.W19(DDR2_CLK_DN3) ; also on sheet 106
M_G_CLK_DP_0: CPU2.AA17(DDR2_CLK_DP0) ; also on sheet 107
M_G_CLK_DP_1: CPU2.AB20(DDR2_CLK_DP1) ; also on sheet 106
M_G_CLK_DP_2: CPU2.AB18(DDR2_CLK_DP2) ; also on sheet 107
M_G_CLK_DP_3: CPU2.AA19(DDR2_CLK_DP3) ; also on sheet 106
M_G_CS_N_0: CPU2.AB16(DDR2_CS0#) ; also on sheet 107
M_G_CS_N_1: CPU2.T16(DDR2_CS1#) ; also on sheet 107
M_G_CS_N_2: CPU2.W13(DDR2_CS2#/CID0) ; also on sheet 107
M_G_CS_N_3: CPU2.AA13(DDR2_CS3#/CID1) ; also on sheet 107
M_G_CS_N_4: CPU2.P16(DDR2_CS4#) ; also on sheet 106
M_G_CS_N_5: CPU2.U15(DDR2_CS5#) ; also on sheet 106
M_G_CS_N_6: CPU2.AC13(DDR2_CS6#/CID3) ; also on sheet 106
M_G_CS_N_7: CPU2.AD16(DDR2_CS7#/CID4) ; also on sheet 106
M_G_DQ_0: CPU2.AD38(DDR2_DQ0) ; also on sheet 106 107
M_G_DQ_1: CPU2.AA37(DDR2_DQ1) ; also on sheet 106 107
M_G_DQ_2: CPU2.R37(DDR2_DQ2) ; also on sheet 106 107
M_G_DQ_3: CPU2.Y38(DDR2_DQ3) ; also on sheet 106 107
M_G_DQ_4: CPU2.AE37(DDR2_DQ4) ; also on sheet 106 107
M_G_DQ_5: CPU2.AC39(DDR2_DQ5) ; also on sheet 106 107
M_G_DQ_6: CPU2.T38(DDR2_DQ6) ; also on sheet 106 107
M_G_DQ_7: CPU2.U37(DDR2_DQ7) ; also on sheet 106 107
M_G_DQ_8: CPU2.V34(DDR2_DQ8) ; also on sheet 106 107
M_G_DQ_9: CPU2.U33(DDR2_DQ9) ; also on sheet 106 107
M_G_DQ_10: CPU2.V30(DDR2_DQ10) ; also on sheet 106 107
M_G_DQ_11: CPU2.T30(DDR2_DQ11) ; also on sheet 106 107
M_G_DQ_12: CPU2.U35(DDR2_DQ12) ; also on sheet 106 107
M_G_DQ_13: CPU2.R35(DDR2_DQ13) ; also on sheet 106 107
M_G_DQ_14: CPU2.T32(DDR2_DQ14) ; also on sheet 106 107
M_G_DQ_15: CPU2.W31(DDR2_DQ15) ; also on sheet 106 107
M_G_DQ_16: CPU2.AD34(DDR2_DQ16) ; also on sheet 106 107
M_G_DQ_17: CPU2.AB34(DDR2_DQ17) ; also on sheet 106 107
M_G_DQ_18: CPU2.AD30(DDR2_DQ18) ; also on sheet 106 107
M_G_DQ_19: CPU2.AB30(DDR2_DQ19) ; also on sheet 106 107
M_G_DQ_20: CPU2.AC35(DDR2_DQ20) ; also on sheet 106 107
M_G_DQ_21: CPU2.AA35(DDR2_DQ21) ; also on sheet 106 107
M_G_DQ_22: CPU2.AE31(DDR2_DQ22) ; also on sheet 106 107
M_G_DQ_23: CPU2.AC31(DDR2_DQ23) ; also on sheet 106 107
M_G_DQ_24: CPU2.U27(DDR2_DQ24) ; also on sheet 106 107
M_G_DQ_25: CPU2.R27(DDR2_DQ25) ; also on sheet 106 107
M_G_DQ_26: CPU2.U23(DDR2_DQ26) ; also on sheet 106 107
M_G_DQ_27: CPU2.R23(DDR2_DQ27) ; also on sheet 106 107
M_G_DQ_28: CPU2.V28(DDR2_DQ28) ; also on sheet 106 107
M_G_DQ_29: CPU2.T28(DDR2_DQ29) ; also on sheet 106 107
M_G_DQ_30: CPU2.V24(DDR2_DQ30) ; also on sheet 106 107
M_G_DQ_31: CPU2.T24(DDR2_DQ31) ; also on sheet 106 107
M_G_DQ_32: CPU2.N9(DDR2_DQ32) ; also on sheet 106 107
M_G_DQ_33: CPU2.K8(DDR2_DQ33) ; also on sheet 106 107
M_G_DQ_34: CPU2.R7(DDR2_DQ34) ; also on sheet 106 107
M_G_DQ_35: CPU2.P6(DDR2_DQ35) ; also on sheet 106 107
M_G_DQ_36: CPU2.J9(DDR2_DQ36) ; also on sheet 106 107
M_G_DQ_37: CPU2.L9(DDR2_DQ37) ; also on sheet 106 107
M_G_DQ_38: CPU2.K6(DDR2_DQ38) ; also on sheet 106 107
M_G_DQ_39: CPU2.M6(DDR2_DQ39) ; also on sheet 106 107
M_G_DQ_40: CPU2.U9(DDR2_DQ40) ; also on sheet 106 107
M_G_DQ_41: CPU2.W11(DDR2_DQ41) ; also on sheet 106 107
M_G_DQ_42: CPU2.AA11(DDR2_DQ42) ; also on sheet 106 107
M_G_DQ_43: CPU2.AB8(DDR2_DQ43) ; also on sheet 106 107
M_G_DQ_44: CPU2.T10(DDR2_DQ44) ; also on sheet 106 107
M_G_DQ_45: CPU2.U11(DDR2_DQ45) ; also on sheet 106 107
M_G_DQ_46: CPU2.AA9(DDR2_DQ46) ; also on sheet 106 107
M_G_DQ_47: CPU2.Y8(DDR2_DQ47) ; also on sheet 106 107
M_G_DQ_48: CPU2.AE11(DDR2_DQ48) ; also on sheet 106 107
M_G_DQ_49: CPU2.AF12(DDR2_DQ49) ; also on sheet 106 107
M_G_DQ_50: CPU2.AK12(DDR2_DQ50) ; also on sheet 106 107
M_G_DQ_51: CPU2.AL13(DDR2_DQ51) ; also on sheet 106 107
M_G_DQ_52: CPU2.AG15(DDR2_DQ52) ; also on sheet 106 107
M_G_DQ_53: CPU2.AF14(DDR2_DQ53) ; also on sheet 106 107
M_G_DQ_54: CPU2.AK14(DDR2_DQ54) ; also on sheet 106 107
M_G_DQ_55: CPU2.AL15(DDR2_DQ55) ; also on sheet 106 107
M_G_DQ_56: CPU2.AG9(DDR2_DQ56) ; also on sheet 106 107
M_G_DQ_57: CPU2.AG7(DDR2_DQ57) ; also on sheet 106 107
M_G_DQ_58: CPU2.AK10(DDR2_DQ58) ; also on sheet 106 107
M_G_DQ_59: CPU2.AL9(DDR2_DQ59) ; also on sheet 106 107
M_G_DQ_60: CPU2.AE7(DDR2_DQ60) ; also on sheet 106 107
M_G_DQ_61: CPU2.AE9(DDR2_DQ61) ; also on sheet 106 107
M_G_DQ_62: CPU2.AK8(DDR2_DQ62) ; also on sheet 106 107
M_G_DQ_63: CPU2.AL7(DDR2_DQ63) ; also on sheet 106 107
M_G_DQS_DN_0: CPU2.W37(DDR2_DQS_DN0) ; also on sheet 106 107
M_G_DQS_DN_1: CPU2.V32(DDR2_DQS_DN1) ; also on sheet 106 107
M_G_DQS_DN_2: CPU2.AD32(DDR2_DQS_DN2) ; also on sheet 106 107
M_G_DQS_DN_3: CPU2.W25(DDR2_DQS_DN3) ; also on sheet 106 107
M_G_DQS_DN_4: CPU2.P8(DDR2_DQS_DN4) ; also on sheet 106 107
M_G_DQS_DN_5: CPU2.Y10(DDR2_DQS_DN5) ; also on sheet 106 107
M_G_DQS_DN_6: CPU2.AJ13(DDR2_DQS_DN6) ; also on sheet 106 107
M_G_DQS_DN_7: CPU2.AH8(DDR2_DQS_DN7) ; also on sheet 106 107
M_G_DQS_DN_8: CPU2.AE25(DDR2_DQS_DN8) ; also on sheet 106 107
M_G_DQS_DN_9: CPU2.AC37(DDR2_DQS_DN9) ; also on sheet 106 107
M_G_DQS_DN_10: CPU2.R33(DDR2_DQS_DN10) ; also on sheet 106 107
M_G_DQS_DN_11: CPU2.AA33(DDR2_DQS_DN11) ; also on sheet 106 107
M_G_DQS_DN_12: CPU2.T26(DDR2_DQS_DN12) ; also on sheet 106 107
M_G_DQS_DN_13: CPU2.L7(DDR2_DQS_DN13) ; also on sheet 106 107
M_G_DQS_DN_14: CPU2.W9(DDR2_DQS_DN14) ; also on sheet 106 107
M_G_DQS_DN_15: CPU2.AJ15(DDR2_DQS_DN15) ; also on sheet 106 107
M_G_DQS_DN_16: CPU2.AJ9(DDR2_DQS_DN16) ; also on sheet 106 107
M_G_DQS_DN_17: CPU2.AB26(DDR2_DQS_DN17) ; also on sheet 106 107
M_G_DQS_DP_0: CPU2.V38(DDR2_DQS_DP0) ; also on sheet 106 107
M_G_DQS_DP_1: CPU2.U31(DDR2_DQS_DP1) ; also on sheet 106 107
M_G_DQS_DP_2: CPU2.AB32(DDR2_DQS_DP2) ; also on sheet 106 107
M_G_DQS_DP_3: CPU2.U25(DDR2_DQS_DP3) ; also on sheet 106 107
M_G_DQS_DP_4: CPU2.N7(DDR2_DQS_DP4) ; also on sheet 106 107
M_G_DQS_DP_5: CPU2.AB10(DDR2_DQS_DP5) ; also on sheet 106 107
M_G_DQS_DP_6: CPU2.AH12(DDR2_DQS_DP6) ; also on sheet 106 107
M_G_DQS_DP_7: CPU2.AJ7(DDR2_DQS_DP7) ; also on sheet 106 107
M_G_DQS_DP_8: CPU2.AC25(DDR2_DQS_DP8) ; also on sheet 106 107
M_G_DQS_DP_9: CPU2.AB38(DDR2_DQS_DP9) ; also on sheet 106 107
M_G_DQS_DP_10: CPU2.T34(DDR2_DQS_DP10) ; also on sheet 106 107
M_G_DQS_DP_11: CPU2.AC33(DDR2_DQS_DP11) ; also on sheet 106 107
M_G_DQS_DP_12: CPU2.V26(DDR2_DQS_DP12) ; also on sheet 106 107
M_G_DQS_DP_13: CPU2.M8(DDR2_DQS_DP13) ; also on sheet 106 107
M_G_DQS_DP_14: CPU2.V8(DDR2_DQS_DP14) ; also on sheet 106 107
M_G_DQS_DP_15: CPU2.AH16(DDR2_DQS_DP15) ; also on sheet 106 107
M_G_DQS_DP_16: CPU2.AH10(DDR2_DQS_DP16) ; also on sheet 106 107
M_G_DQS_DP_17: CPU2.AD26(DDR2_DQS_DP17) ; also on sheet 106 107
M_G_ECC_0: CPU2.AC27(DDR2_ECC0) ; also on sheet 106 107
M_G_ECC_1: CPU2.AA27(DDR2_ECC1) ; also on sheet 106 107
M_G_ECC_2: CPU2.AC23(DDR2_ECC2) ; also on sheet 106 107
M_G_ECC_3: CPU2.AA23(DDR2_ECC3) ; also on sheet 106 107
M_G_ECC_4: CPU2.AD28(DDR2_ECC4) ; also on sheet 106 107
M_G_ECC_5: CPU2.AB28(DDR2_ECC5) ; also on sheet 106 107
M_G_ECC_6: CPU2.AD24(DDR2_ECC6) ; also on sheet 106 107
M_G_ECC_7: CPU2.AB24(DDR2_ECC7) ; also on sheet 106 107
M_G_MA_0: CPU2.L15(DDR2_MA0) ; also on sheet 106 107
M_G_MA_1: CPU2.M16(DDR2_MA1) ; also on sheet 106 107
M_G_MA_2: CPU2.T18(DDR2_MA2) ; also on sheet 106 107
M_G_MA_3: CPU2.L17(DDR2_MA3) ; also on sheet 106 107
M_G_MA_4: CPU2.R19(DDR2_MA4) ; also on sheet 106 107
M_G_MA_5: CPU2.P18(DDR2_MA5) ; also on sheet 106 107
M_G_MA_6: CPU2.M18(DDR2_MA6) ; also on sheet 106 107
M_G_MA_7: CPU2.U19(DDR2_MA7) ; also on sheet 106 107
M_G_MA_8: CPU2.L19(DDR2_MA8) ; also on sheet 106 107
M_G_MA_9: CPU2.P20(DDR2_MA9) ; also on sheet 106 107
M_G_MA_10: CPU2.AA15(DDR2_MA10) ; also on sheet 106 107
M_G_MA_11: CPU2.T20(DDR2_MA11) ; also on sheet 106 107
M_G_MA_12: CPU2.W21(DDR2_MA12) ; also on sheet 106 107
M_G_MA_13: CPU2.P12(DDR2_MA13) ; also on sheet 106 107
M_G_MA_14: CPU2.Y14(DDR2_MA14) ; also on sheet 106 107
M_G_MA_15: CPU2.R13(DDR2_MA15) ; also on sheet 106 107
M_G_MA_16: CPU2.P14(DDR2_MA16) ; also on sheet 106 107
M_G_MA_17: CPU2.T14(DDR2_MA17) ; also on sheet 106 107
M_G_ODT_0: CPU2.Y16(DDR2_ODT0) ; also on sheet 107
M_G_ODT_1: CPU2.W15(DDR2_ODT1) ; also on sheet 107
M_G_ODT_2: CPU2.R15(DDR2_ODT2) ; also on sheet 106
M_G_ODT_3: CPU2.AB14(DDR2_ODT3) ; also on sheet 106
M_G_PAR: CPU2.R17(DDR2_PAR) ; also on sheet 106 107
M_H_ACT_N: CPU2.L21(DDR3_ACT#) ; also on sheet 104 105
M_H_ALERT_N: CPU2.M22(DDR3_ALERT#) ; also on sheet 104 105
M_H_BA_0: CPU2.G13(DDR3_BA0) ; also on sheet 104 105
M_H_BA_1: CPU2.K14(DDR3_BA1) ; also on sheet 104 105
M_H_BG_0: CPU2.J21(DDR3_BG0) ; also on sheet 104 105
M_H_BG_1: CPU2.G21(DDR3_BG1) ; also on sheet 104 105
M_H_C_2: CPU2.J11(DDR3_CID2) ; also on sheet 104 105
M_H_CKE_0: CPU2.F22(DDR3_CKE0) ; also on sheet 105
M_H_CKE_1: CPU2.E21(DDR3_CKE1) ; also on sheet 105
M_H_CKE_2: CPU2.A21(DDR3_CKE2) ; also on sheet 104
M_H_CKE_3: CPU2.D22(DDR3_CKE3) ; also on sheet 104
M_H_CLK_DN_0: CPU2.C17(DDR3_CLK_DN0) ; also on sheet 105
M_H_CLK_DN_1: CPU2.D20(DDR3_CLK_DN1) ; also on sheet 104
M_H_CLK_DN_2: CPU2.D18(DDR3_CLK_DN2) ; also on sheet 105
M_H_CLK_DN_3: CPU2.C19(DDR3_CLK_DN3) ; also on sheet 104
M_H_CLK_DP_0: CPU2.A17(DDR3_CLK_DP0) ; also on sheet 105
M_H_CLK_DP_1: CPU2.B20(DDR3_CLK_DP1) ; also on sheet 104
M_H_CLK_DP_2: CPU2.B18(DDR3_CLK_DP2) ; also on sheet 105
M_H_CLK_DP_3: CPU2.A19(DDR3_CLK_DP3) ; also on sheet 104
M_H_CS_N_0: CPU2.B16(DDR3_CS0#) ; also on sheet 105
M_H_CS_N_1: CPU2.C15(DDR3_CS1#) ; also on sheet 105
M_H_CS_N_2: CPU2.F10(DDR3_CS2#/CID0) ; also on sheet 105
M_H_CS_N_3: CPU2.H10(DDR3_CS3#/CID1) ; also on sheet 105
M_H_CS_N_4: CPU2.A15(DDR3_CS4#) ; also on sheet 104
M_H_CS_N_5: CPU2.F14(DDR3_CS5#) ; also on sheet 104
M_H_CS_N_6: CPU2.G11(DDR3_CS6#/CID3) ; also on sheet 104
M_H_CS_N_7: CPU2.A11(DDR3_CS7#/CID4) ; also on sheet 104
M_H_DQ_0: CPU2.D38(DDR3_DQ0) ; also on sheet 104 105
M_H_DQ_1: CPU2.B38(DDR3_DQ1) ; also on sheet 104 105
M_H_DQ_2: CPU2.L37(DDR3_DQ2) ; also on sheet 104 105
M_H_DQ_3: CPU2.M38(DDR3_DQ3) ; also on sheet 104 105
M_H_DQ_4: CPU2.C39(DDR3_DQ4) ; also on sheet 104 105
M_H_DQ_5: CPU2.J39(DDR3_DQ5) ; also on sheet 104 105
M_H_DQ_6: CPU2.G37(DDR3_DQ6) ; also on sheet 104 105
M_H_DQ_7: CPU2.K38(DDR3_DQ7) ; also on sheet 104 105
M_H_DQ_8: CPU2.A35(DDR3_DQ8) ; also on sheet 104 105
M_H_DQ_9: CPU2.B34(DDR3_DQ9) ; also on sheet 104 105
M_H_DQ_10: CPU2.G31(DDR3_DQ10) ; also on sheet 104 105
M_H_DQ_11: CPU2.E31(DDR3_DQ11) ; also on sheet 104 105
M_H_DQ_12: CPU2.F34(DDR3_DQ12) ; also on sheet 104 105
M_H_DQ_13: CPU2.E35(DDR3_DQ13) ; also on sheet 104 105
M_H_DQ_14: CPU2.D32(DDR3_DQ14) ; also on sheet 104 105
M_H_DQ_15: CPU2.E33(DDR3_DQ15) ; also on sheet 104 105
M_H_DQ_16: CPU2.K34(DDR3_DQ16) ; also on sheet 104 105
M_H_DQ_17: CPU2.M34(DDR3_DQ17) ; also on sheet 104 105
M_H_DQ_18: CPU2.K30(DDR3_DQ18) ; also on sheet 104 105
M_H_DQ_19: CPU2.M30(DDR3_DQ19) ; also on sheet 104 105
M_H_DQ_20: CPU2.J35(DDR3_DQ20) ; also on sheet 104 105
M_H_DQ_21: CPU2.L35(DDR3_DQ21) ; also on sheet 104 105
M_H_DQ_22: CPU2.L31(DDR3_DQ22) ; also on sheet 104 105
M_H_DQ_23: CPU2.N31(DDR3_DQ23) ; also on sheet 104 105
M_H_DQ_24: CPU2.F28(DDR3_DQ24) ; also on sheet 104 105
M_H_DQ_25: CPU2.E27(DDR3_DQ25) ; also on sheet 104 105
M_H_DQ_26: CPU2.F24(DDR3_DQ26) ; also on sheet 104 105
M_H_DQ_27: CPU2.E23(DDR3_DQ27) ; also on sheet 104 105
M_H_DQ_28: CPU2.G29(DDR3_DQ28) ; also on sheet 104 105
M_H_DQ_29: CPU2.E29(DDR3_DQ29) ; also on sheet 104 105
M_H_DQ_30: CPU2.C25(DDR3_DQ30) ; also on sheet 104 105
M_H_DQ_31: CPU2.B24(DDR3_DQ31) ; also on sheet 104 105
M_H_DQ_32: CPU2.K4(DDR3_DQ32) ; also on sheet 104 105
M_H_DQ_33: CPU2.H4(DDR3_DQ33) ; also on sheet 104 105
M_H_DQ_34: CPU2.J1(DDR3_DQ34) ; also on sheet 104 105
M_H_DQ_35: CPU2.L1(DDR3_DQ35) ; also on sheet 104 105
M_H_DQ_36: CPU2.P4(DDR3_DQ36) ; also on sheet 104 105
M_H_DQ_37: CPU2.N3(DDR3_DQ37) ; also on sheet 104 105
M_H_DQ_38: CPU2.K2(DDR3_DQ38) ; also on sheet 104 105
M_H_DQ_39: CPU2.R3(DDR3_DQ39) ; also on sheet 104 105
M_H_DQ_40: CPU2.E9(DDR3_DQ40) ; also on sheet 104 105
M_H_DQ_41: CPU2.F8(DDR3_DQ41) ; also on sheet 104 105
M_H_DQ_42: CPU2.E5(DDR3_DQ42) ; also on sheet 104 105
M_H_DQ_43: CPU2.F6(DDR3_DQ43) ; also on sheet 104 105
M_H_DQ_44: CPU2.C9(DDR3_DQ44) ; also on sheet 104 105
M_H_DQ_45: CPU2.A9(DDR3_DQ45) ; also on sheet 104 105
M_H_DQ_46: CPU2.D6(DDR3_DQ46) ; also on sheet 104 105
M_H_DQ_47: CPU2.G7(DDR3_DQ47) ; also on sheet 104 105
M_H_DQ_48: CPU2.AG3(DDR3_DQ48) ; also on sheet 104 105
M_H_DQ_49: CPU2.AG1(DDR3_DQ49) ; also on sheet 104 105
M_H_DQ_50: CPU2.AL3(DDR3_DQ50) ; also on sheet 104 105
M_H_DQ_51: CPU2.AL5(DDR3_DQ51) ; also on sheet 104 105
M_H_DQ_52: CPU2.AG5(DDR3_DQ52) ; also on sheet 104 105
M_H_DQ_53: CPU2.AE3(DDR3_DQ53) ; also on sheet 104 105
M_H_DQ_54: CPU2.AJ3(DDR3_DQ54) ; also on sheet 104 105
M_H_DQ_55: CPU2.AL1(DDR3_DQ55) ; also on sheet 104 105
M_H_DQ_56: CPU2.V4(DDR3_DQ56) ; also on sheet 104 105
M_H_DQ_57: CPU2.W3(DDR3_DQ57) ; also on sheet 104 105
M_H_DQ_58: CPU2.AC5(DDR3_DQ58) ; also on sheet 104 105
M_H_DQ_59: CPU2.AE5(DDR3_DQ59) ; also on sheet 104 105
M_H_DQ_60: CPU2.U5(DDR3_DQ60) ; also on sheet 104 105
M_H_DQ_61: CPU2.V6(DDR3_DQ61) ; also on sheet 104 105
M_H_DQ_62: CPU2.AC3(DDR3_DQ62) ; also on sheet 104 105
M_H_DQ_63: CPU2.AB6(DDR3_DQ63) ; also on sheet 104 105
M_H_DQS_DN_0: CPU2.C37(DDR3_DQS_DN0) ; also on sheet 104 105
M_H_DQS_DN_1: CPU2.A33(DDR3_DQS_DN1) ; also on sheet 104 105
M_H_DQS_DN_2: CPU2.K32(DDR3_DQS_DN2) ; also on sheet 104 105
M_H_DQS_DN_3: CPU2.G25(DDR3_DQS_DN3) ; also on sheet 104 105
M_H_DQS_DN_4: CPU2.G3(DDR3_DQS_DN4) ; also on sheet 104 105
M_H_DQS_DN_5: CPU2.C7(DDR3_DQS_DN5) ; also on sheet 104 105
M_H_DQS_DN_6: CPU2.AJ1(DDR3_DQS_DN6) ; also on sheet 104 105
M_H_DQS_DN_7: CPU2.AA5(DDR3_DQS_DN7) ; also on sheet 104 105
M_H_DQS_DN_8: CPU2.N25(DDR3_DQS_DN8) ; also on sheet 104 105
M_H_DQS_DN_9: CPU2.H38(DDR3_DQS_DN9) ; also on sheet 104 105
M_H_DQS_DN_10: CPU2.D34(DDR3_DQS_DN10) ; also on sheet 104 105
M_H_DQS_DN_11: CPU2.L33(DDR3_DQS_DN11) ; also on sheet 104 105
M_H_DQS_DN_12: CPU2.D26(DDR3_DQS_DN12) ; also on sheet 104 105
M_H_DQS_DN_13: CPU2.L3(DDR3_DQS_DN13) ; also on sheet 104 105
M_H_DQS_DN_14: CPU2.D8(DDR3_DQS_DN14) ; also on sheet 104 105
M_H_DQS_DN_15: CPU2.AJ5(DDR3_DQS_DN15) ; also on sheet 104 105
M_H_DQS_DN_16: CPU2.W5(DDR3_DQS_DN16) ; also on sheet 104 105
M_H_DQS_DN_17: CPU2.K26(DDR3_DQS_DN17) ; also on sheet 104 105
M_H_DQS_DP_0: CPU2.E37(DDR3_DQS_DP0) ; also on sheet 104 105
M_H_DQS_DP_1: CPU2.B32(DDR3_DQS_DP1) ; also on sheet 104 105
M_H_DQS_DP_2: CPU2.M32(DDR3_DQS_DP2) ; also on sheet 104 105
M_H_DQS_DP_3: CPU2.E25(DDR3_DQS_DP3) ; also on sheet 104 105
M_H_DQS_DP_4: CPU2.H2(DDR3_DQS_DP4) ; also on sheet 104 105
M_H_DQS_DP_5: CPU2.E7(DDR3_DQS_DP5) ; also on sheet 104 105
M_H_DQS_DP_6: CPU2.AK2(DDR3_DQS_DP6) ; also on sheet 104 105
M_H_DQS_DP_7: CPU2.AB4(DDR3_DQS_DP7) ; also on sheet 104 105
M_H_DQS_DP_8: CPU2.L25(DDR3_DQS_DP8) ; also on sheet 104 105
M_H_DQS_DP_9: CPU2.F38(DDR3_DQS_DP9) ; also on sheet 104 105
M_H_DQS_DP_10: CPU2.C35(DDR3_DQS_DP10) ; also on sheet 104 105
M_H_DQS_DP_11: CPU2.J33(DDR3_DQS_DP11) ; also on sheet 104 105
M_H_DQS_DP_12: CPU2.F26(DDR3_DQS_DP12) ; also on sheet 104 105
M_H_DQS_DP_13: CPU2.M4(DDR3_DQS_DP13) ; also on sheet 104 105
M_H_DQS_DP_14: CPU2.B8(DDR3_DQS_DP14) ; also on sheet 104 105
M_H_DQS_DP_15: CPU2.AH4(DDR3_DQS_DP15) ; also on sheet 104 105
M_H_DQS_DP_16: CPU2.Y6(DDR3_DQS_DP16) ; also on sheet 104 105
M_H_DQS_DP_17: CPU2.M26(DDR3_DQS_DP17) ; also on sheet 104 105
M_H_ECC_0: CPU2.L27(DDR3_ECC0) ; also on sheet 104 105
M_H_ECC_1: CPU2.J27(DDR3_ECC1) ; also on sheet 104 105
M_H_ECC_2: CPU2.L23(DDR3_ECC2) ; also on sheet 104 105
M_H_ECC_3: CPU2.J23(DDR3_ECC3) ; also on sheet 104 105
M_H_ECC_4: CPU2.K28(DDR3_ECC4) ; also on sheet 104 105
M_H_ECC_5: CPU2.M28(DDR3_ECC5) ; also on sheet 104 105
M_H_ECC_6: CPU2.M24(DDR3_ECC6) ; also on sheet 104 105
M_H_ECC_7: CPU2.K24(DDR3_ECC7) ; also on sheet 104 105
M_H_MA_0: CPU2.G15(DDR3_MA0) ; also on sheet 104 105
M_H_MA_1: CPU2.K16(DDR3_MA1) ; also on sheet 104 105
M_H_MA_2: CPU2.F16(DDR3_MA2) ; also on sheet 104 105
M_H_MA_3: CPU2.G17(DDR3_MA3) ; also on sheet 104 105
M_H_MA_4: CPU2.J17(DDR3_MA4) ; also on sheet 104 105
M_H_MA_5: CPU2.K18(DDR3_MA5) ; also on sheet 104 105
M_H_MA_6: CPU2.F18(DDR3_MA6) ; also on sheet 104 105
M_H_MA_7: CPU2.J19(DDR3_MA7) ; also on sheet 104 105
M_H_MA_8: CPU2.G19(DDR3_MA8) ; also on sheet 104 105
M_H_MA_9: CPU2.F20(DDR3_MA9) ; also on sheet 104 105
M_H_MA_10: CPU2.L13(DDR3_MA10) ; also on sheet 104 105
M_H_MA_11: CPU2.K20(DDR3_MA11) ; also on sheet 104 105
M_H_MA_12: CPU2.M20(DDR3_MA12) ; also on sheet 104 105
M_H_MA_13: CPU2.M12(DDR3_MA13) ; also on sheet 104 105
M_H_MA_14: CPU2.K12(DDR3_MA14) ; also on sheet 104 105
M_H_MA_15: CPU2.F12(DDR3_MA15) ; also on sheet 104 105
M_H_MA_16: CPU2.J13(DDR3_MA16) ; also on sheet 104 105
M_H_MA_17: CPU2.L11(DDR3_MA17) ; also on sheet 104 105
M_H_ODT_0: CPU2.D16(DDR3_ODT0) ; also on sheet 105
M_H_ODT_1: CPU2.A13(DDR3_ODT1) ; also on sheet 105
M_H_ODT_2: CPU2.D14(DDR3_ODT2) ; also on sheet 104
M_H_ODT_3: CPU2.D12(DDR3_ODT3) ; also on sheet 104
M_H_PAR: CPU2.J15(DDR3_PAR) ; also on sheet 104 105
NV_SAVE_CHA_DIMM0: DIMMA1.230(RFU_2) ; also on sheet 52
PVPP_AB: DIMMA1.142(VPP_0) DIMMA1.143(VPP_1) DIMMA1.284(VDDSPD) DIMMA1.286(VPP_2) DIMMA1.287(VPP_3) DIMMA1.288(VPP_4) ; also on sheet 27 98 116 117 118 160
PVTT_AB: DIMMA1.77(VTT_0) DIMMA1.221(VTT_1) ; also on sheet 29 116 117 118
SMB_DDR_AB_SCL_LVC2V5: DIMMA1.141(SCL) ; also on sheet 116 117 118 160
SMB_DDR_AB_SDA_LVC2V5: DIMMA1.285(SDA) ; also on sheet 116 117 118 160
VSENSE_PVCCIN_CPU1_N: CPU2.BP2(VSS_VCCIN_SENSE) ; also on sheet 32 35
VSENSE_PVCCIN_CPU1_P: CPU2.BN1(VCCIN_SENSE) ; also on sheet 32 35

Not connected (* = marked no-connect by the designer): CPU2 AA43(PE3D_TX_DP14)* AA45(PE3D_TX_DN12)* AA47(PE3C_TX_DN10)* AA49(PE3A_RX_DN3)* AA51(PE3B_RX_DN7)* AA53(PE3B_RX_DN6)* AB22(DDR2_CKE4)* AB44(PE3D_TX_DP13)* AB46(PE3C_TX_DP11)* AB50(PE3B_RX_DP4)* AB52(PE3B_RX_DP5)* AB54(PE2B_RX_DN4)* AB56(PE2B_RX_DN5)* AC43(PE3D_TX_DN14)* AC45(PE3D_TX_DP12)* AC47(PE3C_TX_DP10)* AC49(PE3A_RX_DP3)* AC51(PE3B_RX_DP7)* AC53(PE3B_RX_DP6)* AC55(PE2B_RX_DN6)* AD14(DDR2_ODT5)* AD18(DDR2_CS8#)* AD22(DDR2_CKE5)* AD54(PE2B_RX_DP4)* AD56(PE2B_RX_DP5)* AE17(DDR2_ODT4)* AE55(PE2B_RX_DP6)* AE57(PE2B_RX_DN7)* AF44(PE3A_RX_DN0)* AF46(PE3A_RX_DN2)* AF48(PE3C_RX_DN8)* AF50(PE3C_RX_DN10)* AF58(PE2B_RX_DP7)* AG45(PE3A_RX_DN1)* AG47(PE3D_RX_DN12)* AG49(PE3C_RX_DN11)* AG51(PE3C_RX_DN9)* AG53(PE2B_TX_DN4)* AH44(PE3A_RX_DP0)* AH46(PE3A_RX_DP2)* AH48(PE3C_RX_DP8)* AH50(PE3C_RX_DP10)* AH54(PE2B_TX_DN5)* AH56(PE2C_RX_DN8)* AJ45(PE3A_RX_DP1)* AJ47(PE3D_RX_DP12)* AJ49(PE3C_RX_DP11)* AJ51(PE3C_RX_DP9)* AJ53(PE2B_TX_DP4)* AJ57(PE2C_RX_DN10)* AK54(PE2B_TX_DP5)* AK56(PE2C_RX_DP8)* AK58(PE2C_RX_DN9)* AL57(PE2C_RX_DP10)* AM46(PE3D_RX_DN14)* AM50(PE2A_TX_DN1)* AM52(PE2A_TX_DN3)* AM58(PE2C_RX_DP9)* AN45(PE3D_RX_DN15)* AN47(PE3D_RX_DN13)* AN49(PE2A_TX_DN0)* AN51(PE2A_TX_DN2)* AN53(PE2B_TX_DN6)* AP46(PE3D_RX_DP14)* AP50(PE2A_TX_DP1)* AP52(PE2A_TX_DP3)* AP54(PE2B_TX_DN7)* AP56(PE2D_RX_DN13)* AR45(PE3D_RX_DP15)* AR47(PE3D_RX_DP13)* AR49(PE2A_TX_DP0)* AR51(PE2A_TX_DP2)* AR53(PE2B_TX_DP6)* AR57(PE2C_RX_DN11)* AT54(PE2B_TX_DP7)* AT56(PE2D_RX_DP13)* AT58(PE2D_RX_DN12)* AU57(PE2C_RX_DP11)* AV48(PE2D_TX_DN14)* AV50(PE2D_TX_DN12)* AV52(PE2C_TX_DN8)* AV58(PE2D_RX_DP12)* AW47(PE2D_TX_DN15)* AW49(PE2D_TX_DN13)* AW51(PE2C_TX_DN11)* AW53(PE2C_TX_DN9)* AY48(PE2D_TX_DP14)* AY50(PE2D_TX_DP12)* AY52(PE2C_TX_DP8)* AY54(PE2C_TX_DN10)* AY56(PE2D_RX_DN15)* AY58(PE2D_RX_DN14)* B12(DDR3_CS9#)* B14(DDR3_CS8#)* B22(DDR3_CKE4)* B42(DMI_TX_DN3)* B44(DMI_TX_DN1)* B48(DMI_RX_DN2)* B50(DMI_RX_DN0)* BA47(PE2D_TX_DP15)* BA49(PE2D_TX_DP13)* BA51(PE2C_TX_DP11)* BA53(PE2C_TX_DP9)* BA57(PE2D_RX_DP14)* BB54(PE2C_TX_DP10)* BB56(PE2D_RX_DP15)* C43(DMI_TX_DN2)* C45(DMI_TX_DN0)* C47(DMI_RX_DN3)* C49(DMI_RX_DN1)* C51(PE1A_RX_DN0)* D42(DMI_TX_DP3)* D44(DMI_TX_DP1)* D48(DMI_RX_DP2)* D50(DMI_RX_DP0)* D52(PE1A_RX_DN1)* D54(PE1A_RX_DN2)* E11(DDR3_ODT5)* E13(DDR3_ODT4)* E43(DMI_TX_DP2)* E45(DMI_TX_DP0)* E47(DMI_RX_DP3)* E49(DMI_RX_DP1)* E51(PE1A_RX_DP0)* E55(PE1A_RX_DN3)* F52(PE1A_RX_DP1)* F54(PE1A_RX_DP2)* G55(PE1A_RX_DP3)* H42(PE1A_TX_DN0)* H44(PE1A_TX_DN2)* H46(PE1B_TX_DN4)* H48(PE1B_TX_DN6)* H50(PE3A_TX_DN0)* J43(PE1A_TX_DN1)* J45(PE1A_TX_DN3)* J47(PE1B_TX_DN5)* J49(PE1B_TX_DN7)* J51(PE3A_TX_DN1)* J53(PE1B_RX_DN4)* J57(PE1B_RX_DN6)* K22(DDR3_CKE5)* K42(PE1A_TX_DP0)* K44(PE1A_TX_DP2)* K46(PE1B_TX_DP4)* K48(PE1B_TX_DP6)* K50(PE3A_TX_DP0)* K54(PE1B_RX_DN5)* K56(PE1B_RX_DN7)* L43(PE1A_TX_DP1)* L45(PE1A_TX_DP3)* L47(PE1B_TX_DP5)* L49(PE1B_TX_DP7)* L51(PE3A_TX_DP1)* L53(PE1B_RX_DP4)* L55(PE2A_RX_DN0)* L57(PE1B_RX_DP6)* M54(PE1B_RX_DP5)* M56(PE1B_RX_DP7)* N55(PE2A_RX_DP0)* P44(PE3D_TX_DP15)* P46(PE3C_TX_DN8)* P48(PE3A_TX_DN3)* P50(PE3B_TX_DN6)* P52(PE3B_TX_DN4)* R45(PE3C_TX_DN9)* R47(PE3A_TX_DN2)* R49(PE3B_TX_DN7)* R51(PE3B_TX_DN5)* T12(DDR2_CS9#)* T44(PE3D_TX_DN15)* T46(PE3C_TX_DP8)* T48(PE3A_TX_DP3)* T50(PE3B_TX_DP6)* T52(PE3B_TX_DP4)* T54(PE2A_RX_DN1)* T56(PE2A_RX_DN2)* U45(PE3C_TX_DP9)* U47(PE3A_TX_DP2)* U49(PE3B_TX_DP7)* U51(PE3B_TX_DP5)* U55(PE2A_RX_DN3)* V54(PE2A_RX_DP1)* V56(PE2A_RX_DP2)* W55(PE2A_RX_DP3)* Y44(PE3D_TX_DN13)* Y46(PE3C_TX_DN11)* Y50(PE3B_RX_DN4)* Y52(PE3B_RX_DN5)*; DIMMA1 144(RFU_3)* 205(RFU_0)* 227(RFU_1)* NP1* NP2* NP3*

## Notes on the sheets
sheet 119
- DDR4 DIMM CPU0 CHA-1
- FAB1 REV021 20150424
- Four chip selects are
  connected to a DIMM slot
  to support up to Quad rank DIMMs
- FAB1 REV003 20150318
- I2C Address = A0
- DIMMA1
- Chip Select Signal DIMM Mapping
- ODT Signal DIMM Mapping
- CKE Signal DIMM Mapping
- DDR4 Clock Signal DIMM Pin Mapping (UDIMM/RDIMM support)
- DIMM
- DIMM Pin
- CPU Signal
- DIMM
- DIMM Pin
- CPU Signal
- DIMM
- DIMM Pin
- CPU Signal
- DIMM
- DIMM Pin
- CPU Signal
- DIMM0
- 84
- CS_N0
- DIMM0
- 87
- ODT0
- DIMM0
- 60
- CKE0
- DIMM0
- 74
- CLK_DP0
- DIMM0
- 89
- CS_N1
- DIMM0
- 91
- ODT1
- DIMM0
- 203
- CKE1
- DIMM0
- 75
- CLK_DN0
- DIMM0
- 93
- CS_N2/C[0]
- DIMM1
- 87
- ODT2
- DIMM1
- 60
- CKE2
- DIMM0
- 218
- CLK_DP2
- DIMM0
- 237
- CS_N3/C[1]
- DIMM1
- 91
- ODT3
- DIMM1
- 203
- CKE3
- DIMM0
- 219
- CLK_DN2
- DIMM1
- 84
- CS_N4
- DIMM1
- 74
- CLK_DP1
- DIMM1
- 89
- CS_N5
- DIMM1
- 75
- CLK_DN1
- DIMM1
- 93
- CS_N6/C[3]
- DIMM1
- 218
- CLK_DP3
- DIMM1
- 237
- CS_N7/C[4]
- DIMM1
- 219
- CLK_DN3
sheet 120
- CPU2 - VCCIN & VDDQ
sheet 121
- CPU2 - PCIE (3A-3D)
sheet 122
- CPU2 - PCIE (2A-2D)
sheet 123
- CPU2 - DMI & PCIE (1A-1B)
- FAB1 REV025 20150502
- FAB1 REV025 20150502
- Remove test points
sheet 124
- CPU2 - DDR4 (CHANNEL H)
- FAB1 REV003 20150318
sheet 125
- CPU2 - DDR4 (CHANNEL G)
- FAB1 REV003 20150318
